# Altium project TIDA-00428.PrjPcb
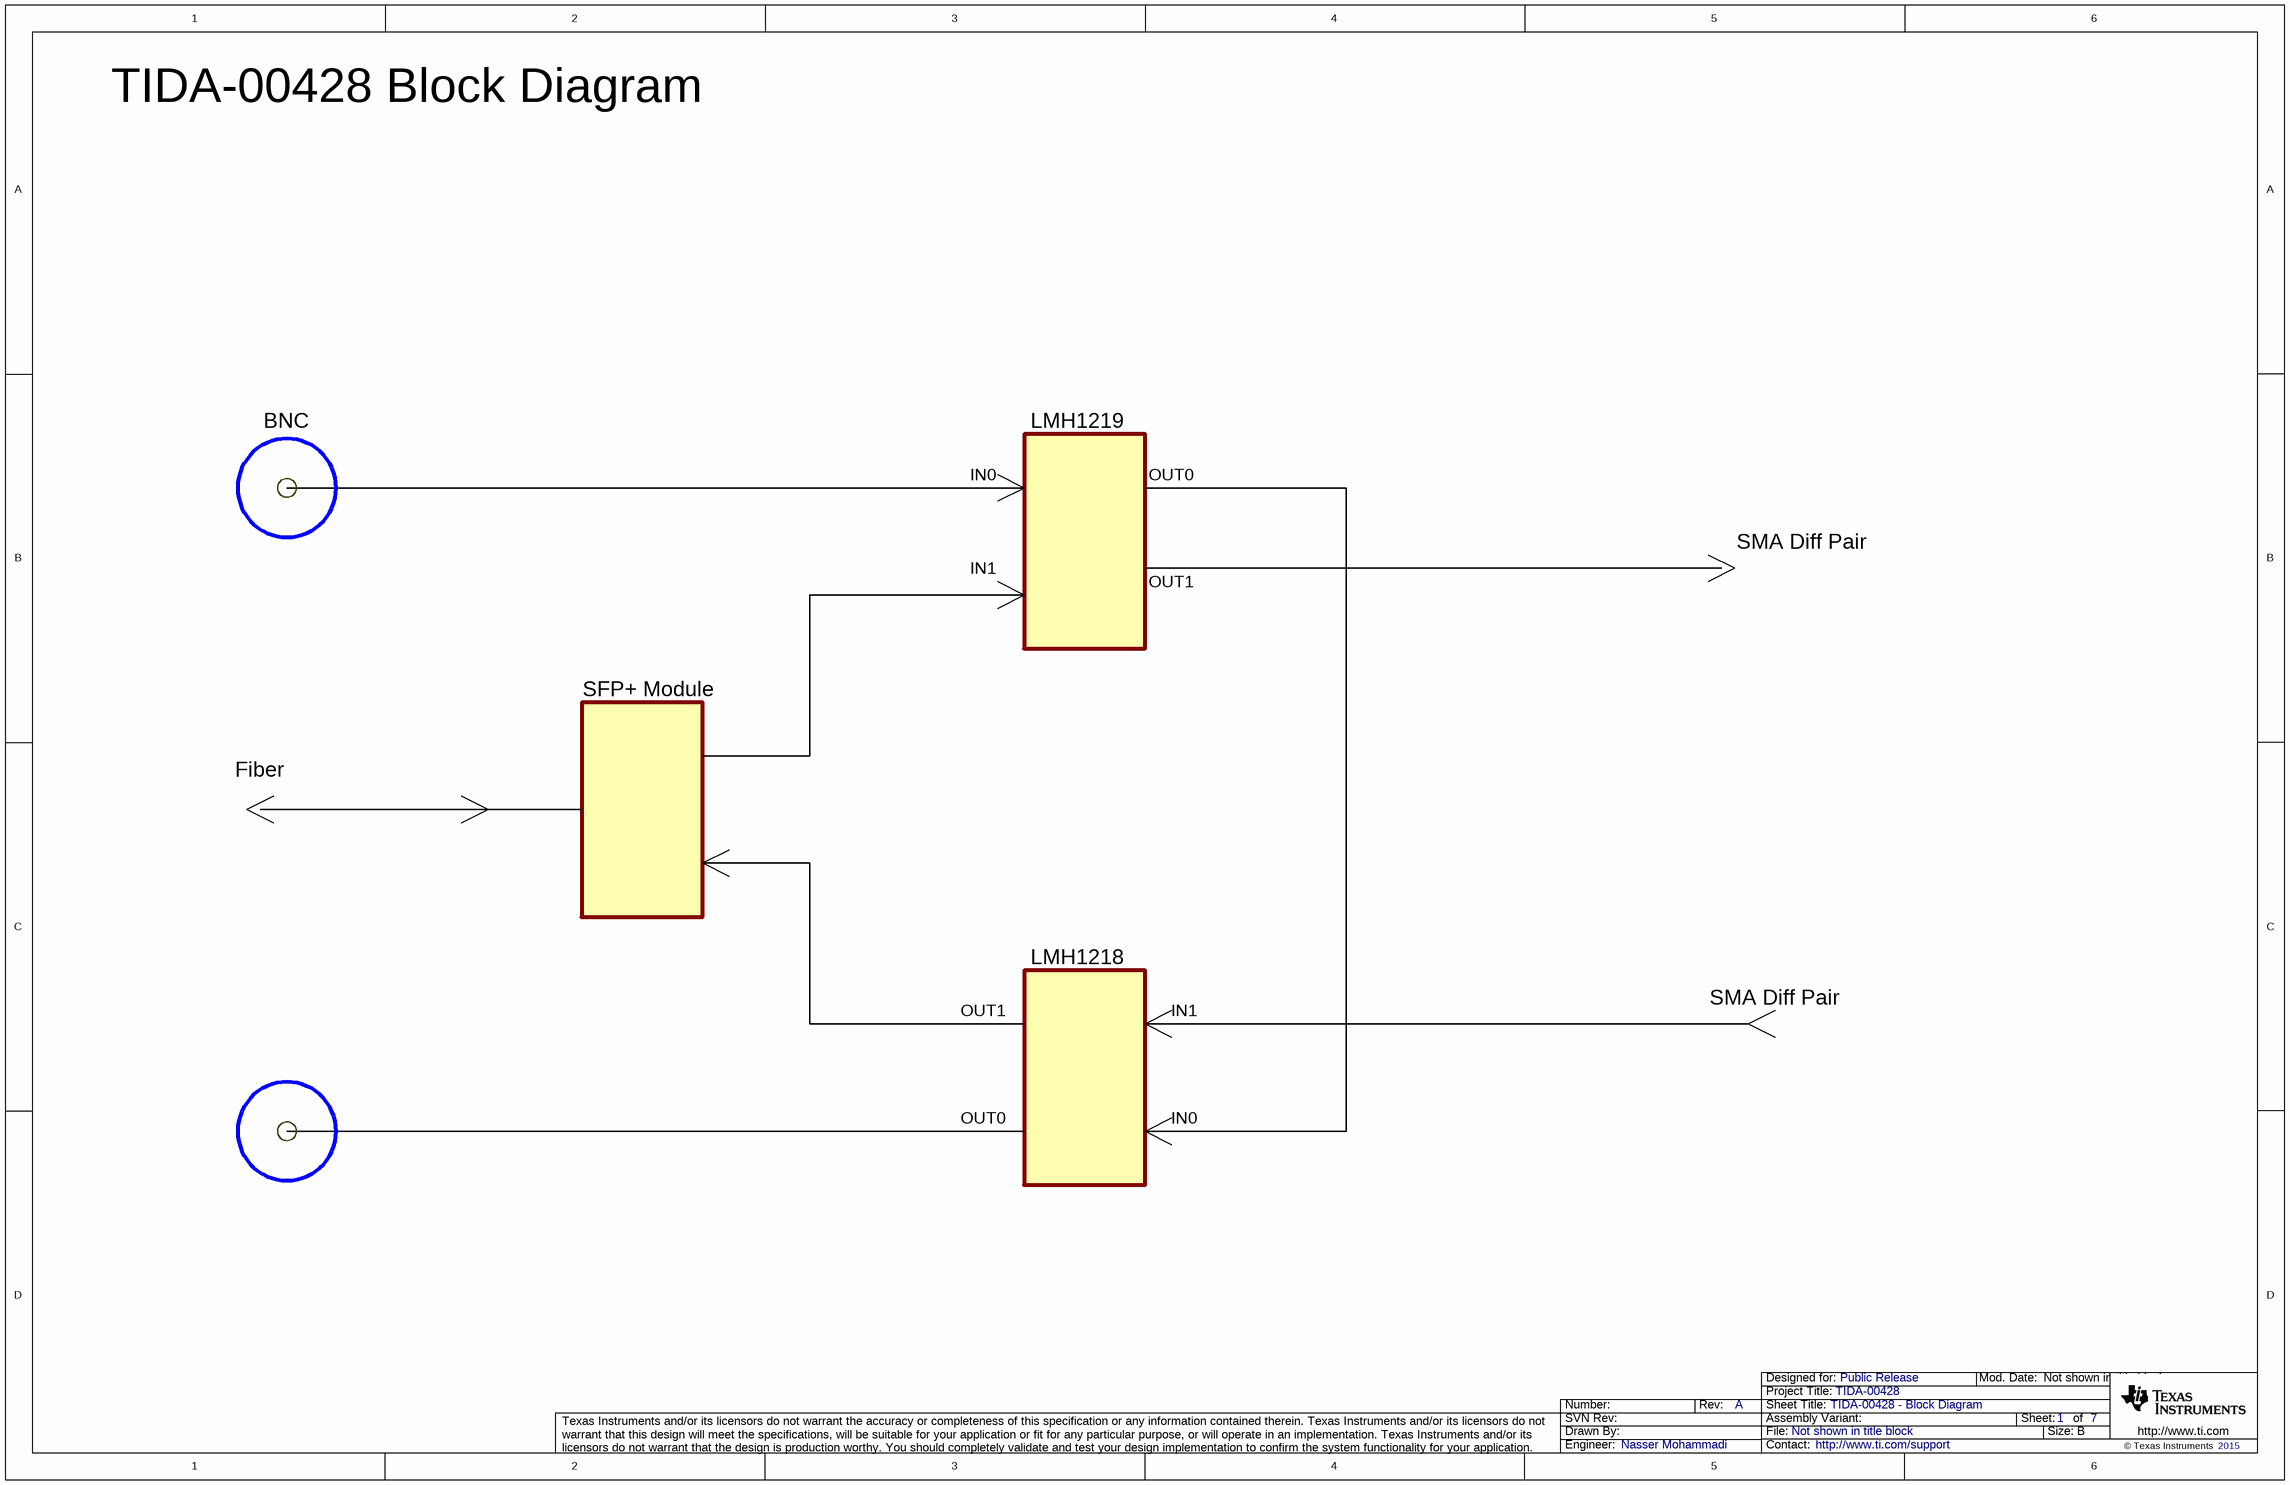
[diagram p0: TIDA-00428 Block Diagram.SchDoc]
CopyrightYear: 2015; PCB_Rev: A; PRJ_Customer: Public Release; PRJ_Engineer: Nasser Mohammadi; PRJ_Title: TIDA-00428; SCH_Rev: A; TechSupport: http://www.ti.com/support
7 sheets, 146 parts. Net scope: global (net labels, ports and power ports of the same name join across sheets).
Sheets:
  TIDA-00428 Block Diagram.SchDoc
  TIDA-00428 LMH1219_Schematic.SchDoc
  TIDA-00428 USB_CNTRL.SchDoc
  TIDA-00428 LMH1218_Schematic.SchDoc
  TIDA-00428 Molex_SFP_Connector.SchDoc
  TIDA-00428 Hardware_ANSI-B.SchDoc
  TIDA-00428 Power.SchDoc

## Sheet TIDA-00428 Block Diagram.SchDoc: TIDA-00428 - Block Diagram
size 431 x 279 mm; Date: Not shown in title block; ApprovedBy: Not shown in title block; CheckedBy: Not shown in title block; Author: Not shown in title block; CompanyName: Not shown in title block; Engineer: Not shown in title block; Organization: Not shown in title block; Address1: Not shown in title block; Address2: Not shown in title block; Address3: Not shown in title block; Address4: Not shown in title block; DocumentNumber: 1; Revision: Use project parameter SCH_Rev; SheetNumber: 1; SheetTotal: 7; PageSetup: Record=PageOptions¦CenterHorizontal=True¦CenterVertical=True¦PrintScale=1.00¦XCorrection=1.00¦YCorrection=1.00¦PrintKind=0¦BorderSize=5000000¦LeftOffset=0¦BottomOffset=0¦Orientation=2¦PaperLength=1000¦PaperWidth=1000¦Scale=100¦PaperSource=15¦PrintQuality=600¦MediaType=1¦DitherType=10¦PaperKind=Letter¦PrintScaleMode=1

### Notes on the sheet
- TIDA-00428 Block Diagram
- BNC
- LMH1219
- IN0
- OUT0
- IN1
- SMA Diff Pair
- OUT1
- SFP+ Module
- Fiber
- LMH1218

## Sheet TIDA-00428 LMH1219_Schematic.SchDoc: TIDA-00428 - LMH1219
size 431 x 279 mm; Date: Not shown in title block; ApprovedBy: Not shown in title block; CheckedBy: Not shown in title block; Author: Not shown in title block; CompanyName: Not shown in title block; Engineer: NasserM; Organization: Not shown in title block; Address1: Not shown in title block; Address2: Not shown in title block; Address3: Not shown in title block; Address4: Not shown in title block; DocumentNumber: 1; Revision: A; SheetNumber: 2; SheetTotal: 7; PageSetup: Record=PageOptions¦CenterHorizontal=True¦CenterVertical=True¦PrintScale=0.59¦XCorrection=1.00¦YCorrection=1.00¦PrintKind=0¦BorderSize=5000000¦LeftOffset=0¦BottomOffset=0¦Orientation=2¦PaperLength=1000¦PaperWidth=1000¦Scale=100¦PaperSource=15¦PrintQuality=600¦MediaType=1¦DitherType=10¦PaperKind=Letter¦PrintScaleMode=1
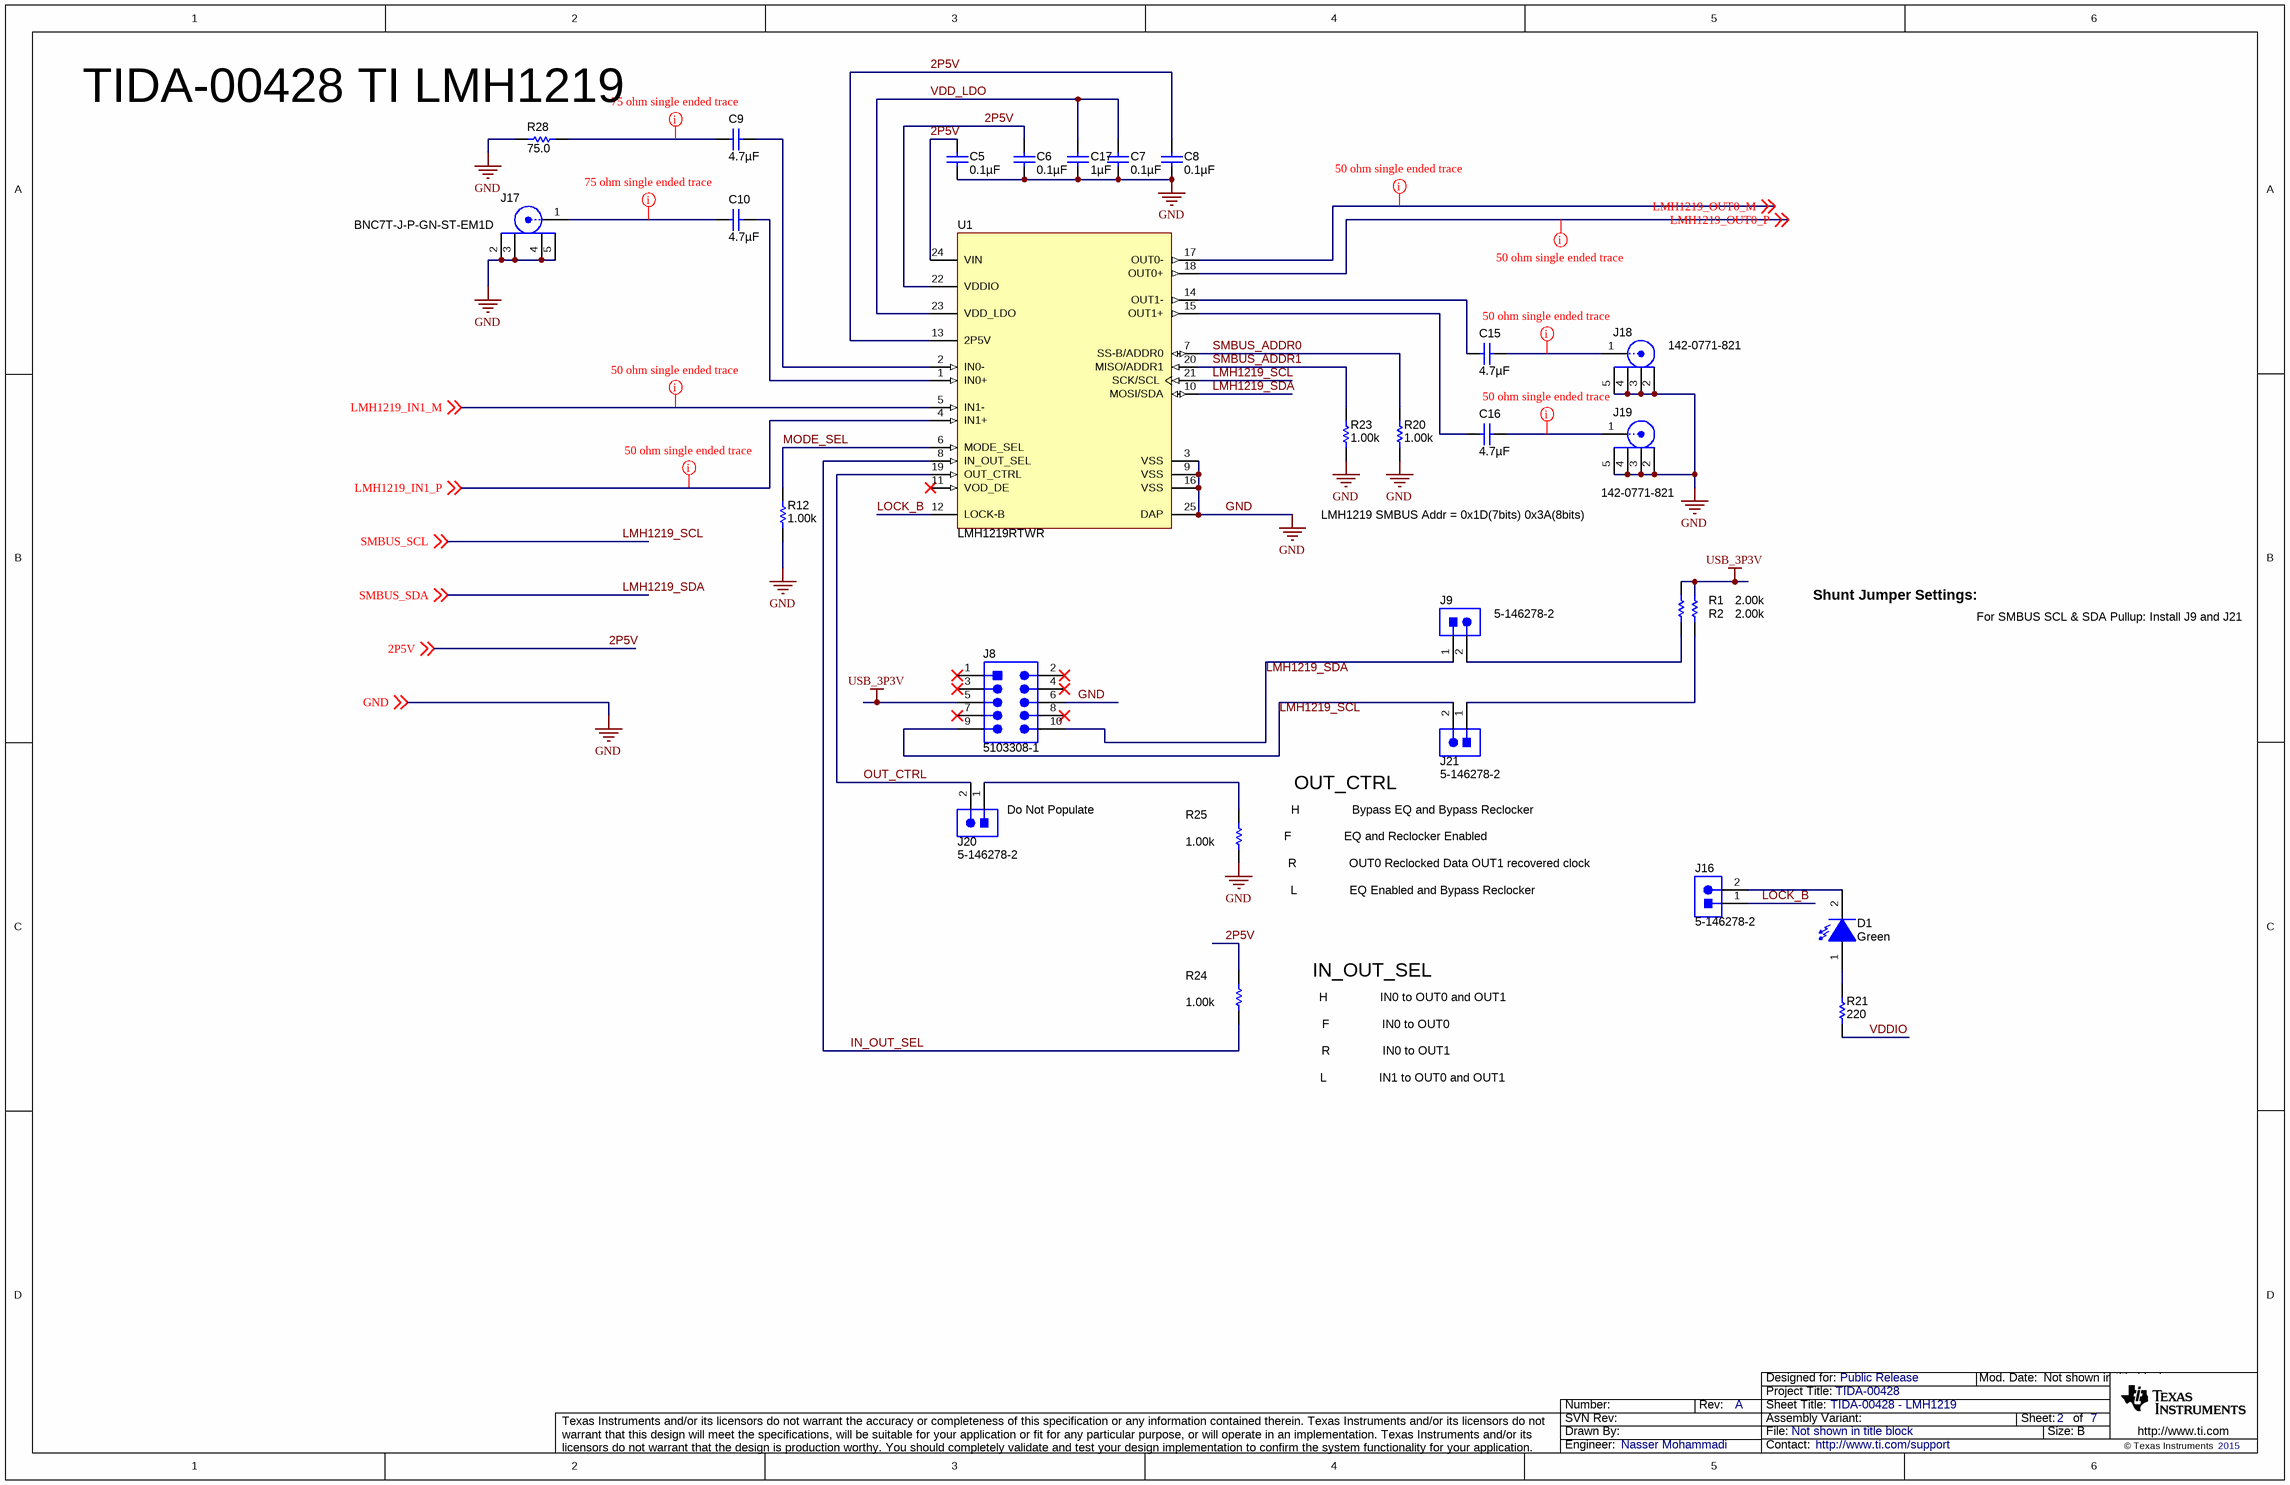
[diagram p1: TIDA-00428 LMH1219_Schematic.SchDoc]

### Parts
C5  ValueDisplayed: 0.1µF  [0402]  (hidden comment: C1005X5R0J104K)
C6  ValueDisplayed: 0.1µF  [0402]  (hidden comment: C1005X5R0J104K)
C7  ValueDisplayed: 0.1µF  [0402]  (hidden comment: C1005X5R0J104K)
C8  ValueDisplayed: 0.1µF  [0402]  (hidden comment: C1005X5R0J104K)
C9  ValueDisplayed: 4.7µF  [0402S]  (hidden comment: C1005X5R1A475K050BC)
C10  ValueDisplayed: 4.7µF  [0402S]  (hidden comment: C1005X5R1A475K050BC)
C15  ValueDisplayed: 4.7µF  [0402S]  (hidden comment: C1005X5R1A475K050BC)
C16  ValueDisplayed: 4.7µF  [0402S]  (hidden comment: C1005X5R1A475K050BC)
C17  ValueDisplayed: 1µF  [0402]  (hidden comment: C1005X5R0J105M)
D1  value Green  [LED_SML-LX0603GW]  (hidden comment: SML-LX0603GW-TR)
J8  5103308-1  [CONN_5103308-1]
J9  5-146278-2  [TE_5-146278-2]
J16  5-146278-2  [TE_5-146278-2]
J17  BNC7T-J-P-GN-ST-EM1D  [SAMTEC_BNC7T-J-P-GN-ST-EM1D]
J18  142-0771-821  [Emerson_142-0771-821]
J19  142-0771-821  [Emerson_142-0771-821]
J20  5-146278-2  [TE_5-146278-2]
J21  5-146278-2  [TE_5-146278-2]
R1  value 2.00k  [0402]  (hidden comment: CRCW04022K00FKED)
R2  value 2.00k  [0402]  (hidden comment: CRCW04022K00FKED)
R12  value 1.00k  [0402]  (hidden comment: CRCW04021K00FKED)
R20  value 1.00k  [0402]  (hidden comment: CRCW04021K00FKED)
R21  value 220  [0402]  (hidden comment: CRCW0402220RJNED)
R23  value 1.00k  [0402]  (hidden comment: CRCW04021K00FKED)
R24  value 1.00k  [0402]  (hidden comment: CRCW04021K00FKED)
R25  value 1.00k  [0402]  (hidden comment: CRCW04021K00FKED)
R28  value 75.0  [0402]  (hidden comment: CRCW040275R0FKED)
U1  LMH1219RTWR  [RTW0024A]

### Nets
2P5V: C5.1 C6.1 C8.1 R24.2 U1.13(2P5V) U1.22(VDDIO) U1.24(VIN) ; off-sheet 2P5V
GND: C5.2 C6.2 C7.2 C8.2 C17.2 J8.6 J17.2 J17.3 J17.4 J17.5 J18.2 J18.3 J18.4 J18.5 J19.2 J19.3 J19.4 J19.5 R12.1 R20.1 R23.1 R25.1 R28.2 U1.3(VSS) U1.9(VSS) U1.16(VSS) U1.25(DAP) ; off-sheet GND
USB_3P3V: J8.5 R1.2 R2.2
IN_OUT_SEL: R24.1 U1.8(IN_OUT_SEL)
LMH1219_IN1_M: U1.5(IN1-) ; off-sheet LMH1219_IN1_M
LMH1219_IN1_P: U1.4(IN1+) ; off-sheet LMH1219_IN1_P
LMH1219_OUT0_M: U1.17(OUT0-) ; off-sheet LMH1219_OUT0_M
LMH1219_OUT0_P: U1.18(OUT0+) ; off-sheet LMH1219_OUT0_P
LMH1219_SCL: J8.9 J21.2 U1.21(SCK/SCL) ; off-sheet SMBUS_SCL  [also labelled SMBUS_SCL]  [project net GPIO1/I2C_SCL]
LMH1219_SDA: J8.10 J9.1 U1.10(MOSI/SDA) ; off-sheet SMBUS_SDA  [also labelled SMBUS_SDA]  [project net GPIO0/I2C_SDA]
LOCK_B: J16.1 U1.12(LOCK-B)
MODE_SEL: R12.2 U1.6(MODE_SEL)
OUT_CTRL: J20.2 U1.19(OUT_CTRL)
SMBUS_ADDR0: R20.2 U1.7(SS-B/ADDR0)
SMBUS_ADDR1: R23.2 U1.20(MISO/ADDR1)
VDD_LDO: C7.1 C17.1 U1.23(VDD_LDO)
VDDIO: R21.1
NetC9_1: C9.1 U1.2(IN0-)
NetC9_2: C9.2 R28.1
NetC10_1: C10.1 U1.1(IN0+)
NetC10_2: C10.2 J17.1
NetC15_1: C15.1 J18.1
NetC15_2: C15.2 U1.14(OUT1-)
NetC16_1: C16.1 J19.1
NetC16_2: C16.2 U1.15(OUT1+)
NetD1_1: D1.1(A) R21.2
NetD1_2: D1.2(K) J16.2
NetJ9_2: J9.2 R1.1
NetJ20_1: J20.1 R25.2
NetJ21_1: J21.1 R2.1

Not connected (* = marked no-connect by the designer): J8 1* 2* 3* 4* 7* 8*; U1 11(VOD_DE)*

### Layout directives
rule Undefined: LMH1219_IN1_M, LMH1219_IN1_P, LMH1219_OUT0_M, LMH1219_OUT0_P, NetC9_2, NetC10_2, NetC15_1, NetC16_1

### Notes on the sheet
- (near R28) TIDA-00428 TI LMH1219
- LMH1219 SMBUS Addr = 0x1D(7bits) 0x3A(8bits)
- Shunt Jumper Settings:
- For SMBUS SCL & SDA Pullup: Install J9 and J21
- (near J20) Do Not Populate
- OUT_CTRL
- (near R25) F               EQ and Reclocker Enabled
- (near R25) H               Bypass EQ and Bypass Reclocker
- (near R25) L               EQ Enabled and Bypass Reclocker
- (near R25) R               OUT0 Reclocked Data OUT1 recovered clock
- IN_OUT_SEL
- F               IN0 to OUT0
- H               IN0 to OUT0 and OUT1
- R               IN0 to OUT1
- L               IN1 to OUT0 and OUT1

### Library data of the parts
C5-C8 = C1005X5R0J104K: CAP, CERM, 0.1uF, 6.3V, +/-10%, X5R, 0402; Manufacturer: TDK; Polarized: N; CompType: Capacitor; U/M: EA; Cap_F: 0.0000001; Tolerance_%: 10; ESR_Ohm: 0.0186; Value1: 0.0186 ohm; VDC_V: 6.3; TaMin_C: -55; TaMax_C: 85
C9 C10 C15 C16 = C1005X5R1A475K050BC: CAP, CERM, 4.7 µF, 10 V, +/- 10%, X5R, 0402; Manufacturer: TDK; Polarized: N; CompType: Capacitor; Value: 4.7uF; U/M: EA; Cap_F: 0.0000047; Tolerance_%: 10; Value1: Unknown; Value2: 10V; TaMin_C: -55; TaMax_C: 85; Cap_Case: 0402
C17 = C1005X5R0J105M: CAP, CERM, 1 µF, 6.3 V, +/- 20%, X5R, 0402; Manufacturer: TDK; Polarized: N; CompType: Capacitor; Value: 1uF; U/M: EA; Cap_F: 0.000001; Tolerance_%: 20; ESR_ohm: 0.0079; Value1: 0.0079 ohm; VDC_V: 6.3; Value2: 6.3V; TaMin_C: -55; TaMax_C: 85
D1 = SML-LX0603GW-TR: LED, Green, SMD; Manufacturer: Lumex; Vf_V: 2.2; Value2: 2.2V; Io_A: 0.02; Tjmax_C: 85; Value1: W; U/M: EA
J8 = 5103308-1: Header (shrouded), 100mil, 5x2, Gold, TH; Manufacturer: TE Connectivity; SymbolCreator: a0412235; U/M: EA
J9 J16 J20 J21 = 5-146278-2: Header, 100mil, 2x1, Tin, TH; Manufacturer: TE Connectivity; SymbolCreator: a0412235; U/M: EA
J17 = BNC7T-J-P-GN-ST-EM1D: Connector, BNC Edge Mount, SMD; Manufacturer: Samtec; SymbolCreator: Altium; U/M: EA
J18 J19 = 142-0771-821: Connector, TH, End launch SMA 50 ohm; Manufacturer: Emerson Network Power; SymbolCreator: X0208326; U/M: EA
R1 R2 = CRCW04022K00FKED: RES, 2.00k ohm, 1%, 0.063W, 0402; Manufacturer: Vishay-Dale; CompType: Resistor; Res_ohm: 2000; Value_Code: 2k00; Tolerance_%: 1; Power_W: 0.063; VDC_V: 50; TempCo: 100 ppm/C; EIA_Code: E96; U/M: EA
R12 R20 R23-R25 = CRCW04021K00FKED: RES, 1.00k ohm, 1%, 0.063W, 0402; Manufacturer: Vishay-Dale; CompType: Resistor; Res_ohm: 1000; Value_Code: 1k00; Tolerance_%: 1; Power_W: 0.063; VDC_V: 50; TempCo: 100 ppm/C; EIA_Code: E96; U/M: EA
R21 = CRCW0402220RJNED: RES, 220 ohm, 5%, 0.063W, 0402; Manufacturer: Vishay-Dale; CompType: Resistor; Value_Code: 220R; Tolerance_%: 5; Power_W: 0.063; VDC_V: 50; TempCo: 200 ppm/C; EIA_Code: E24; U/M: EA
R28 = CRCW040275R0FKED: RES, 75.0 ohm, 1%, 0.063W, 0402; Manufacturer: Vishay-Dale; CompType: Resistor; Res_ohm: 75; Value_Code: 75R0; Tolerance_%: 1; Power_W: 0.063; VDC_V: 50; TempCo: 100 ppm/C; EIA_Code: E96; U/M: EA
U1 = LMH1219RTWR: Low Power 12G UHD Adaptive Cable Equalizer with Integrated Reclocker, RTW0024A; Alternate PartNumber: LMH1219RTWT; Manufacturer: Texas Instruments; SymbolCreator: Altium; CompType: IC; U/M: EA

## Sheet TIDA-00428 USB_CNTRL.SchDoc: TIDA-00428 - USB_CNTRL
size 431 x 279 mm; Date: Not shown in title block; ApprovedBy: Not shown in title block; CheckedBy: Not shown in title block; Author: Not shown in title block; CompanyName: Not shown in title block; DrawnBy: Michael Hinh; Engineer: Not shown in title block; Organization: Not shown in title block; Address1: Not shown in title block; Address2: Not shown in title block; Address3: Not shown in title block; Address4: Not shown in title block; DocumentNumber: 1; Revision: Use project parameter SCH_Rev; SheetNumber: 5; SheetTotal: 7; PageSetup: Record=PageOptions¦CenterHorizontal=True¦CenterVertical=True¦PrintScale=1.00¦XCorrection=1.00¦YCorrection=1.00¦PrintKind=0¦BorderSize=5000000¦LeftOffset=0¦BottomOffset=0¦Orientation=2¦PaperLength=1000¦PaperWidth=1000¦Scale=100¦PaperSource=15¦PrintQuality=600¦MediaType=1¦DitherType=10¦PaperKind=Letter¦PrintScaleMode=1
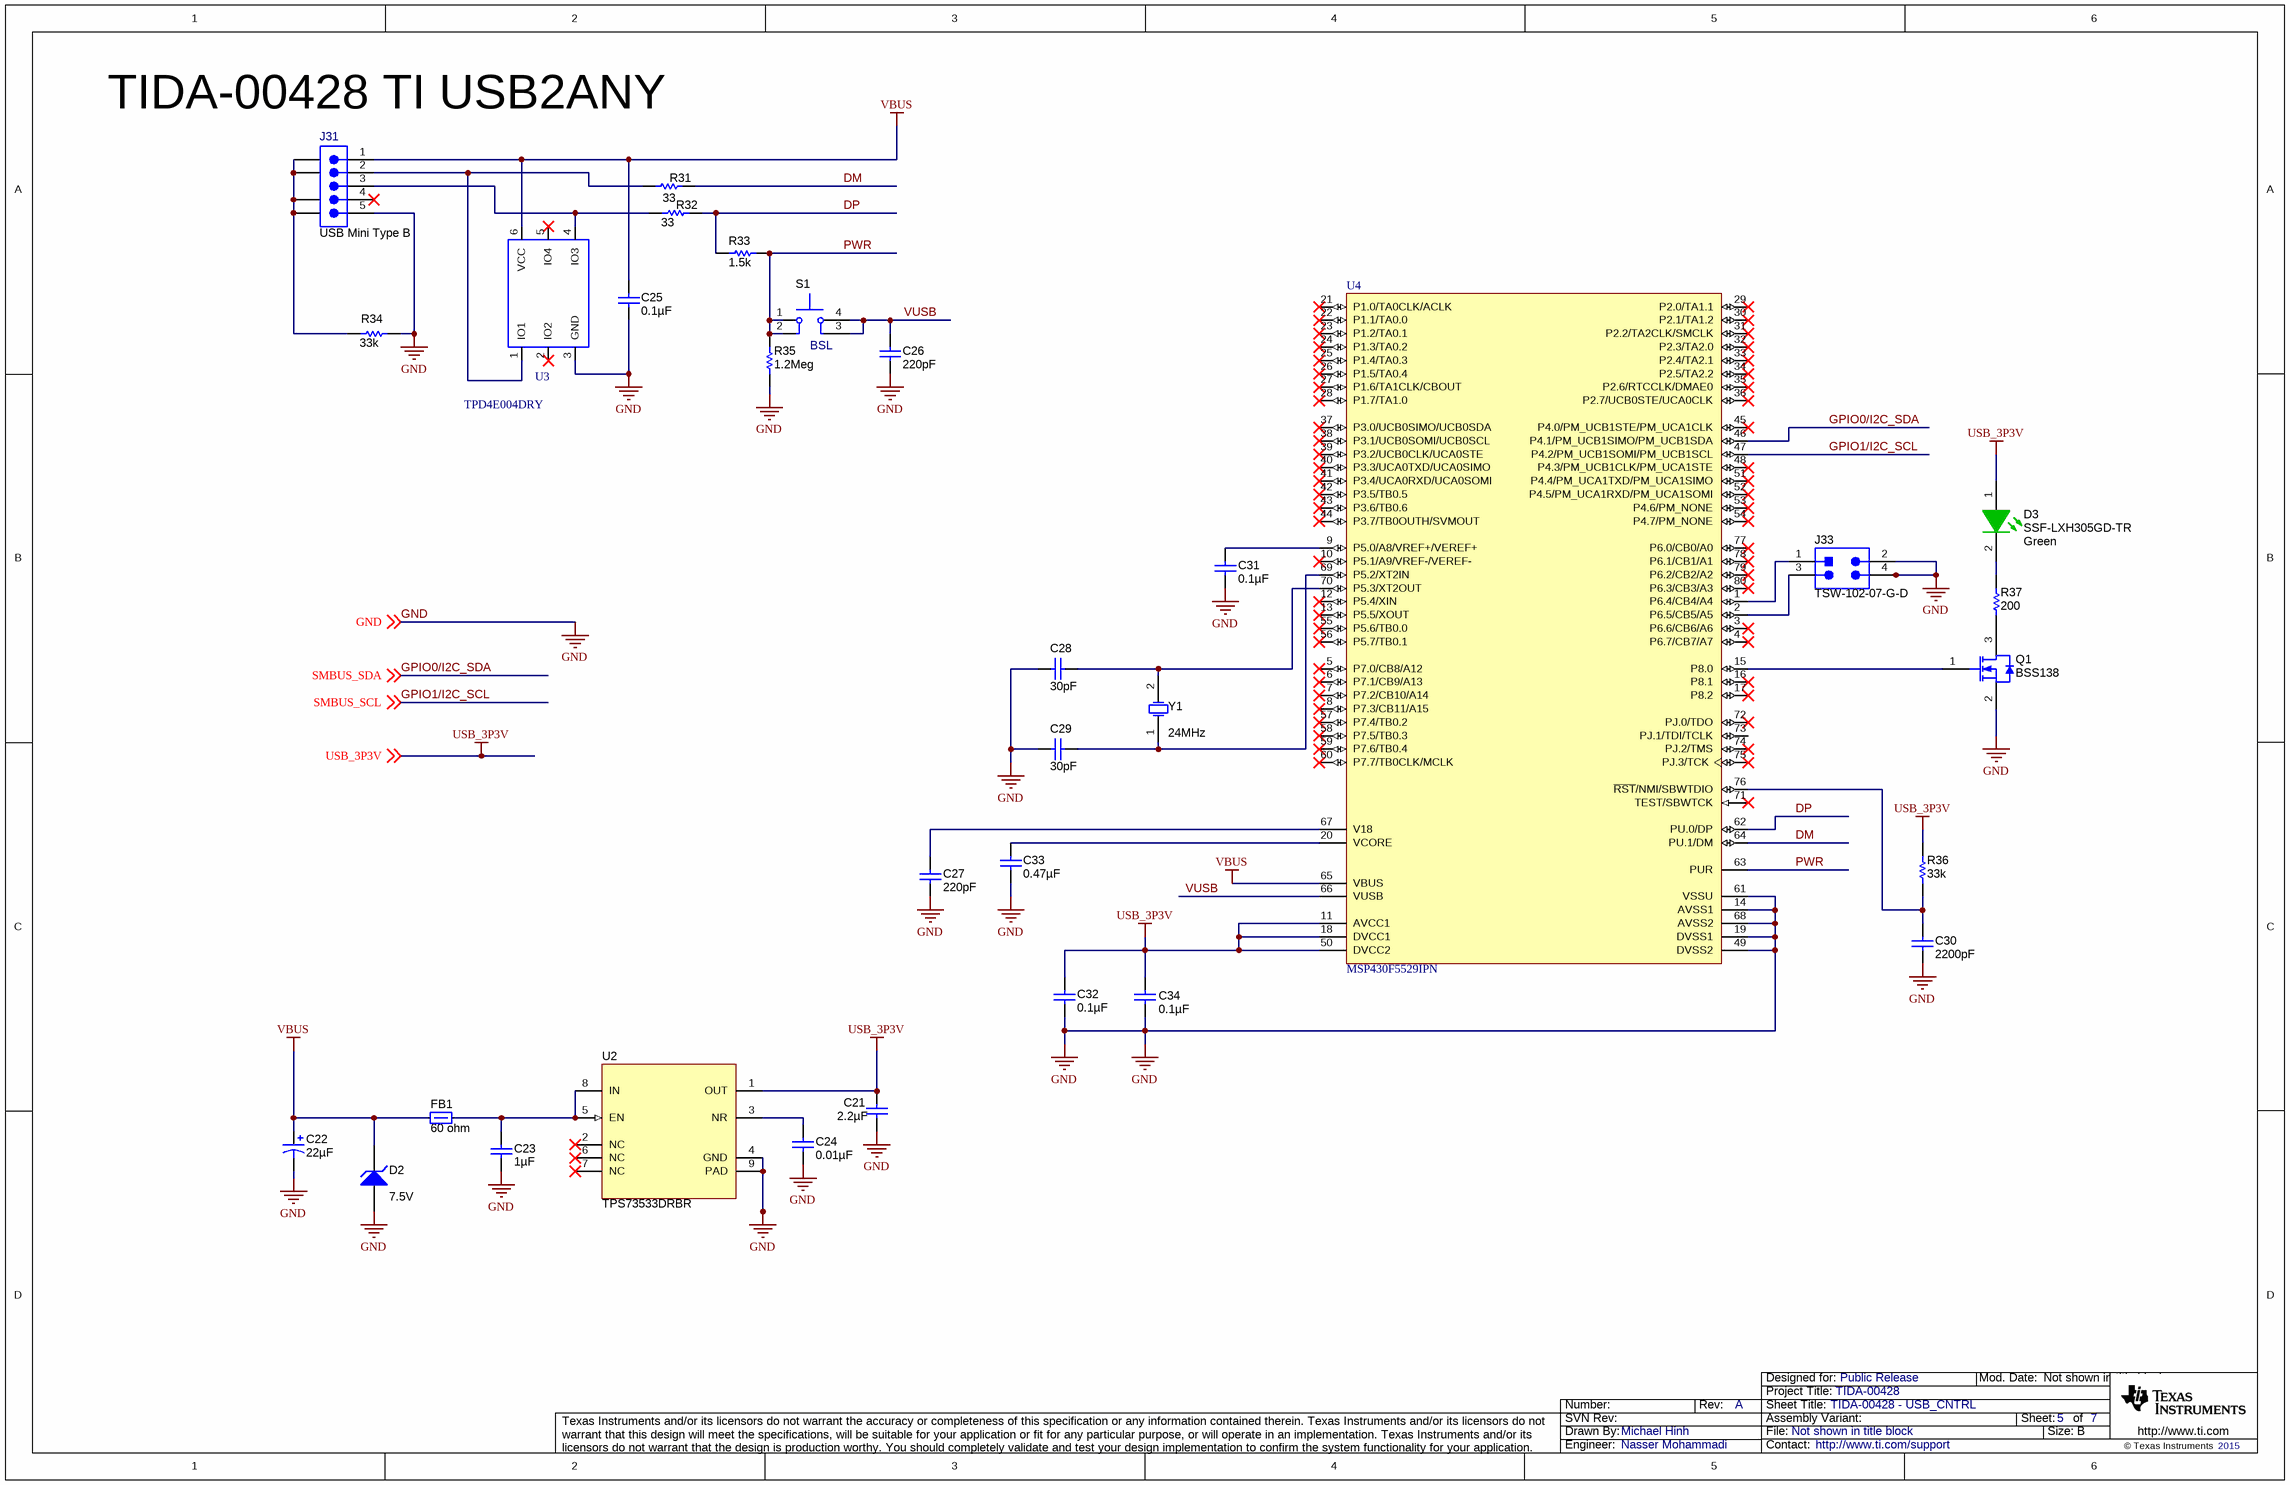
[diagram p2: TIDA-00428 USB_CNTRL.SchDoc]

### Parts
C21  ValueDisplayed: 2.2µF  [C0805]  (hidden comment: 0805YD225KAT2A)
C22  ValueDisplayed: 22µF  [CAPSMT_62_E55]  (hidden comment: EEE-1AA220WR)
C23  ValueDisplayed: 1µF  [C0805]  (hidden comment: C2012X7R1C105K/1.25)
C24  ValueDisplayed: 0.01µF  [C603]  (hidden comment: C1608X7R1H103K)
C25  ValueDisplayed: 0.1µF  [C603]  (hidden comment: 0603YC104JAT2A)
C26  ValueDisplayed: 220pF  [C603]  (hidden comment: 06035A221FAT2A)
C27  ValueDisplayed: 220pF  [C603]  (hidden comment: 06035A221FAT2A)
C28  ValueDisplayed: 30pF  [C603]  (hidden comment: GRM1885C2A300JA01D)
C29  ValueDisplayed: 30pF  [C603]  (hidden comment: GRM1885C2A300JA01D)
C30  ValueDisplayed: 2200pF  [C603]  (hidden comment: C0603X222K5RACTU)
C31  ValueDisplayed: 0.1µF  [C603]  (hidden comment: 0603YC104JAT2A)
C32  ValueDisplayed: 0.1µF  [C603]  (hidden comment: 0603YC104JAT2A)
C33  ValueDisplayed: 0.47µF  [C603]  (hidden comment: GRM188R71A474KA61D)
C34  ValueDisplayed: 0.1µF  [C603]  (hidden comment: 0603YC104JAT2A)
D2  value 7.5V  [SMB]  (hidden comment: 1SMB5922BT3G)
D3  SSF-LXH305GD-TR  value Green  [SSF-LXH305GD_Green]
FB1  value 60 ohm  [0603]  (hidden comment: BK1608HS600-T)
J31  USB Mini Type B  [CONN_USB-Mini-B-1734035-2]
J33  TSW-102-07-G-D  [TSW-102-07-G-D]
Q1  BSS138  [SOT-23]
R31  value 33  [0402]  (hidden comment: CRCW040233R0JNED)
R32  value 33  [0402]  (hidden comment: CRCW040233R0JNED)
R33  value 1.5k  [0402]  (hidden comment: CRCW04021K50JNED)
R34  value 33k  [0402]  (hidden comment: CRCW040233K0JNED)
R35  value 1.2Meg  [R603]  (hidden comment: CRCW06031M20JNEA)
R36  value 33k  [0402]  (hidden comment: CRCW040233K0JNED)
R37  value 200  [R603]  (hidden comment: CRCW0603200RFKEA)
S1  EVQ-PSD02K  [SW_EVQ-PSD02K]  (value not drawn)
U2  TPS73533DRBR  [DRB0008A]
U3  TPD4E004DRY  [DRY]
U4  MSP430F5529IPN  [PN0080A_N]
Y1  Frequency: 24MHz  [XTAL_CSM-7X]  (hidden comment: ECS-240-20-5PX-TR)

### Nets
GND: C21.1 C22.2(-) C23.1 C24.1 C25.1 C26.1 C27.1 C28.2 C29.2 C30.1 C31.1 C32.1 C33.1 C34.1 D2.2(A) J31.5 J33.2 J33.4 Q1.2(S) R34.1 R35.1 U2.4(GND) U2.9(PAD) U3.3(GND) U4.14(AVSS1) U4.19(DVSS1) U4.49(DVSS2) U4.61(VSSU) U4.68(AVSS2) ; off-sheet GND
USB_3P3V: C21.2 C32.2 C34.2 D3.1(A) R36.1 U2.1(OUT) U4.11(AVCC1) U4.18(DVCC1) U4.50(DVCC2) ; off-sheet USB_3P3V
VBUS: C22.1(+) C25.2 D2.1(K) FB1.1 J31.1 U3.6(VCC) U4.65(VBUS)
DM: R31.1 U4.64(PU.1/DM)
DP: R32.1 R33.2 U4.62(PU.0/DP)
GPIO0/I2C_SDA: U4.46(P4.1/PM_UCB1SIMO/PM_UCB1SDA) ; off-sheet SMBUS_SDA  [also labelled SMBUS_SDA]
GPIO1/I2C_SCL: U4.47(P4.2/PM_UCB1SOMI/PM_UCB1SCL) ; off-sheet SMBUS_SCL  [also labelled SMBUS_SCL]
PWR: R33.1 R35.2 S1.1 S1.2 U4.63(PUR)
VUSB: C26.2 S1.3 S1.4 U4.66(VUSB)
NetC23_2: C23.2 FB1.2 U2.5(EN) U2.8(IN)
NetC24_2: C24.2 U2.3(NR)
NetC27_2: C27.2 U4.67(V18)
NetC28_1: C28.1 U4.70(P5.3/XT2OUT) Y1.2(OSC2)
NetC29_1: C29.1 U4.69(P5.2/XT2IN) Y1.1(OSC1)
NetC30_2: C30.2 R36.2 U4.76(~{RST}/NMI/SBWTDIO)
NetC31_2: C31.2 U4.9(P5.0/A8/VREF+/VEREF+)
NetC33_2: C33.2 U4.20(VCORE)
NetD3_2: D3.2(K) R37.2
NetJ31_2: J31.2 R31.2 U3.1(IO1)
NetJ31_3: J31.3 R32.2 U3.4(IO3)
NetJ31_6: J31.6(GND) J31.7(GND) J31.8(GND) J31.9(GND) R34.2
NetJ33_1: J33.1 U4.1(P6.4/CB4/A4)
NetJ33_3: J33.3 U4.2(P6.5/CB5/A5)
NetQ1_1: Q1.1(G) U4.15(P8.0)
NetQ1_3: Q1.3(D) R37.1

Not connected (* = marked no-connect by the designer): J31 4*; U2 2(NC)* 6(NC)* 7(NC)*; U3 2(IO2)* 5(IO4)*; U4 3(P6.6/CB6/A6)* 4(P6.7/CB7/A7)* 5(P7.0/CB8/A12)* 6(P7.1/CB9/A13)* 7(P7.2/CB10/A14)* 8(P7.3/CB11/A15)* 10(P5.1/A9/VREF-/VEREF-)* 12(P5.4/XIN)* 13(P5.5/XOUT)* 16(P8.1)* 17(P8.2)* 21(P1.0/TA0CLK/ACLK)* 22(P1.1/TA0.0)* 23(P1.2/TA0.1)* 24(P1.3/TA0.2)* 25(P1.4/TA0.3)* 26(P1.5/TA0.4)* 27(P1.6/TA1CLK/CBOUT)* 28(P1.7/TA1.0)* 29(P2.0/TA1.1)* 30(P2.1/TA1.2)* 31(P2.2/TA2CLK/SMCLK)* 32(P2.3/TA2.0)* 33(P2.4/TA2.1)* 34(P2.5/TA2.2)* 35(P2.6/RTCCLK/DMAE0)* 36(P2.7/UCB0STE/UCA0CLK)* 37(P3.0/UCB0SIMO/UCB0SDA)* 38(P3.1/UCB0SOMI/UCB0SCL)* 39(P3.2/UCB0CLK/UCA0STE)* 40(P3.3/UCA0TXD/UCA0SIMO)* 41(P3.4/UCA0RXD/UCA0SOMI)* 42(P3.5/TB0.5)* 43(P3.6/TB0.6)* 44(P3.7/TB0OUTH/SVMOUT)* 45(P4.0/PM_UCB1STE/PM_UCA1CLK)* 48(P4.3/PM_UCB1CLK/PM_UCA1STE)* 51(P4.4/PM_UCA1TXD/PM_UCA1SIMO)* 52(P4.5/PM_UCA1RXD/PM_UCA1SOMI)* 53(P4.6/PM_NONE)* 54(P4.7/PM_NONE)* 55(P5.6/TB0.0)* 56(P5.7/TB0.1)* 57(P7.4/TB0.2)* 58(P7.5/TB0.3)* 59(P7.6/TB0.4)* 60(P7.7/TB0CLK/MCLK)* 71(TEST/SBWTCK)* 72(PJ.0/TDO)* 73(PJ.1/TDI/TCLK) 74(PJ.2/TMS)* 75(PJ.3/TCK)* 77(P6.0/CB0/A0)* 78(P6.1/CB1/A1)* 79(P6.2/CB2/A2)* 80(P6.3/CB3/A3)*

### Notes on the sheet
- (near J31) TIDA-00428 TI USB2ANY
- (near S1) BSL

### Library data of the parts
C21 = 0805YD225KAT2A: CAP, CERM, 2.2uF, 16V, +/-10%, X5R, 0805; Manufacturer: AVX; Polarized: N; CompType: Capacitor; U/M: EA; Cap_F: 0.0000022; Tolerance_%: 10; ESR_Ohm: 0.009; Value1: 0.009 ohm; VDC_V: 16; TaMin_C: -55; TaMax_C: 85; Cap_Case: 0805
C22 = EMVE100ADA220ME55G: CAP ALUM 22UF 10V 20% SMD; Manufacturer: Panasonic - ECG; Polarized: Y; CompType: Capacitor; U/M: EA; Cap_F: 0.000022; Tolerance_%: 20; VDC_V: 10; IRMS_A: 0.03; TaMin_C: -40; TaMax_C: 105; Cap_Case: E55
C23 = C2012Y5V1C105Z/0.85: CAP CER 1UF 16V 10% X7R 0805; Manufacturer: TDK; Polarized: N; CompType: Capacitor; U/M: EA; Cap_F: 0.000001; Tolerance_%: 80; ESR_Ohm: 0.009; Value1: 0.009 ohm; VDC_V: 16; TaMin_C: -30; TaMax_C: 85; Cap_Case: 0805
C24 = C1608X7R1H103K: CAP, CERM, 0.01uF, 50V, +/-10%, X7R, 0603; Manufacturer: TDK; Polarized: N; CompType: Capacitor; U/M: EA; Cap_F: 0.00000001; Tolerance_%: 10; ESR_Ohm: 0.0539; Value1: 0.0539 ohm; VDC_V: 50; TaMin_C: -55; TaMax_C: 125; Cap_Case: 0603
C25 C31 C32 C34 = 0603YC104JAT2A: CAP, CERM, 0.1uF, 16V, +/-5%, X7R, 0603; Manufacturer: AVX; Polarized: N; CompType: Capacitor; U/M: EA; Cap_F: 0.0000001; Tolerance_%: 5; ESR_Ohm: 0.039; Value1: 0.039 ohm; VDC_V: 16; TaMin_C: -55; TaMax_C: 125; Cap_Case: 0603
C26 C27 = 06035A221FAT2A: CAP, CERM, 220pF, 50V, +/-1%, C0G/NP0, 0603; Manufacturer: AVX; Polarized: N; CompType: Capacitor; U/M: EA; Cap_F: 0.00000000022; Tolerance_%: 1; ESR_Ohm: 0.083; Value1: 0.083 ohm; VDC_V: 50; TaMin_C: -55; TaMax_C: 125; Cap_Case: 0603
C28 C29 = GRM1885C2A300JA01D: CAP, CERM, 30pF, 100V, +/-5%, C0G/NP0, 0603; Manufacturer: MuRata; Polarized: N; CompType: Capacitor; U/M: EA; Cap_F: 0.00000000003; Tolerance_%: 5; VDC_V: 100; TaMin_C: -55; TaMax_C: 125; Cap_Case: 0603
C30 = C0603X222K5RACTU: CAP, CERM, 2200pF, 50V, +/-10%, X7R, 0603; Manufacturer: Kemet; Polarized: N; CompType: Capacitor; U/M: EA; Cap_F: 0.0000000022; Tolerance_%: 10; VDC_V: 50; TaMin_C: -55; TaMax_C: 125; Cap_Case: 0603
C33 = GRM188R71A474KA61D: CAP, CERM, 0.47uF, 10V, +/-10%, X7R, 0603; Manufacturer: MuRata; Polarized: N; CompType: Capacitor; U/M: EA; Cap_F: 0.00000047; Tolerance_%: 10; TaMin_C: -55; TaMax_C: 125; Cap_Case: 0603
D2 = 1SMB5922BT3G: Diode, Zener, 7.5 V, 550 mW, SMB; Manufacturer: ON Semiconductor; SymbolCreator: a0412235; U/M: EA; Power_W: 0.55; Vz_V: 7.5; Value1: 0.55W; RJA_CperW: 226
D3 = SSF-LXH305GD-TR: LED, Green, SMD; Manufacturer: Lumex; SymbolCreator: Altium; Vf_V: 2.2; Value2: 2.2V; Io_A: 0.02; Vr_V: 5; Ir_A: 0.0001; Tjmax_C: 85; Value1: W; Angle: 60; U/M: EA
FB1 = BK1608HS600-T: Ferrite Bead, 60 ohm @ 100 MHz, 0.8 A, 0603; Manufacturer: Taiyo Yuden; Imax_A: 0.8; DCR_ohm: 0.1; Value1: 0.1 ohm; Value2: 0.8A; ZTyp@100MHz_Ohm: 60
J31 = 1734035-2: Connector, Receptacle, Mini-USB Type B, R/A, Top Mount SMT; Manufacturer: TE Connectivity; SymbolCreator: A0412235; U/M: EA
J33 = TSW-102-07-G-D: Header, 100mil, 2x2, Gold, TH; Manufacturer: Samtec; SymbolCreator: a0412235; U/M: EA
Q1 = BSS138: MOSFET, N-CH, 50 V, 0.22 A, SOT-23; Manufacturer: Fairchild Semiconductor; Alternate Manufacturer: None; U/M: EA; ChType: N; Value: 50V; VdsMax_V: 50; Value1: 6 ohm; Rdson45_ohm: 6; Value2: 1.7 nC; QgTyp_nC: 1.7; Vgs_V: 20; IdsMax_A: 0.22
R31 R32 = CRCW040233R0JNED: RES, 33 ohm, 5%, 0.063W, 0402; Manufacturer: Vishay-Dale; CompType: Resistor; Value_Code: 33R0; Tolerance_%: 5; Power_W: 0.063; VDC_V: 50; TempCo: 200 ppm/C; EIA_Code: E24; U/M: EA
R33 = CRCW04021K50JNED: RES, 1.5k ohm, 5%, 0.063W, 0402; Manufacturer: Vishay-Dale; CompType: Resistor; Res_ohm: 1500; Value_Code: 1k50; Tolerance_%: 5; Power_W: 0.063; VDC_V: 50; TempCo: 200 ppm/C; EIA_Code: E24; U/M: EA
R34 R36 = CRCW040233K0JNED: RES, 33k ohm, 5%, 0.063W, 0402; Manufacturer: Vishay-Dale; CompType: Resistor; Res_ohm: 33000; Value_Code: 33k0; Tolerance_%: 5; Power_W: 0.063; VDC_V: 50; TempCo: 200 ppm/C; EIA_Code: E24; U/M: EA
R35 = CRCW06031M20JNEA: RES, 1.2Meg ohm, 5%, 0.1W, 0603; Manufacturer: Vishay-Dale; CompType: Resistor; Res_ohm: 1200000; Value_Code: 1M20; Tolerance_%: 5; Power_W: 0.1; VDC_V: 75; TempCo: 200 ppm/C; EIA_Code: E24; U/M: EA
R37 = CRCW0603200RFKEA: RES, 200 ohm, 1%, 0.1W, 0603; Manufacturer: Vishay-Dale; CompType: Resistor; Value_Code: 200R; Tolerance_%: 1; Power_W: 0.1; VDC_V: 75; TempCo: 100 ppm/C; EIA_Code: E96; U/M: EA
S1 = EVQ-PSD02K: Switch, Tactile, SPST-NO, SMT; Manufacturer: Panasonic; SymbolCreator: a0799628; VDC_V: 12; SwitchFunction: Off-Mom; PositionCount: 1; CurrentRating_mA: 50
U2 = TPS73533DRBR: 500mA, Low Quiescent Current, Ultra-Low Noise, High PSRR Low-Dropout Linear Regulator, DRB0008A; Manufacturer: Texas Instruments; Alternate PartNumber: TPS73533DRBT; SymbolCreator: Altium; CompType: IC; U/M: EA
U3 = TPD4E004DRY: IC, 4-Chan ESD-Protection Array; Manufacturer: Texas Instruments; Second Source: C:\program files\p-cad 2004\pcad_pdf's\tpd4e004.pdf; Reference: \\vette02\pmp_pcb\pcad_pdf's\tpd4e004.pdf; Area: 3.883 mm
U4 = MSP430F5529IPN: 25 MHz Mixed Signal Microcontroller with 128 KB Flash, 8192 B SRAM and 63 GPIOs, -40 to 85 degC, 80-pin QFP (PN), Green (RoHS & no Sb/Br); Manufacturer: Texas Instruments; Alternate PartNumber: Equivalent; ADC: 12-bit SAR; ADC Channels: 16; Brown Out Reset: Yes; DMA: 3; Flash(KB): 128; Frequency(MHz): 25; GPIO: 63; Multiplier: 32x32; Pin/Package: 0DIESALE, 80LQFP; SRAM(B): 8192; SubFamily: 5 Series; Timers - 16-bit: 4; USB: 1; USCI_A (UART/LIN/IrDA/SPI): 2
Y1 = ECS-240-20-5PX-TR: Crystal, 24.000MHz, 20pF, SMD; Manufacturer: ECS Inc.; SymbolCreator: a0412235; U/M: EA; TaMin_C: -10; TaMax_C: 70; Frequency Stability: ±50ppm

## Sheet TIDA-00428 LMH1218_Schematic.SchDoc: TIDA-00428 - LMH1218
size 431 x 279 mm; Date: Not shown in title block; ApprovedBy: Not shown in title block; CheckedBy: Not shown in title block; Author: Not shown in title block; CompanyName: Not shown in title block; Engineer: Nasser; Organization: Not shown in title block; Address1: Not shown in title block; Address2: Not shown in title block; Address3: Not shown in title block; Address4: Not shown in title block; DocumentNumber: 1; Revision: Use project parameter SCH_Rev; SheetNumber: 3; SheetTotal: 7; PageSetup: Record=PageOptions¦CenterHorizontal=True¦CenterVertical=True¦PrintScale=1.00¦XCorrection=1.00¦YCorrection=1.00¦PrintKind=0¦BorderSize=5000000¦LeftOffset=0¦BottomOffset=0¦Orientation=2¦PaperLength=1000¦PaperWidth=1000¦Scale=100¦PaperSource=15¦PrintQuality=600¦MediaType=1¦DitherType=10¦PaperKind=Letter¦PrintScaleMode=1
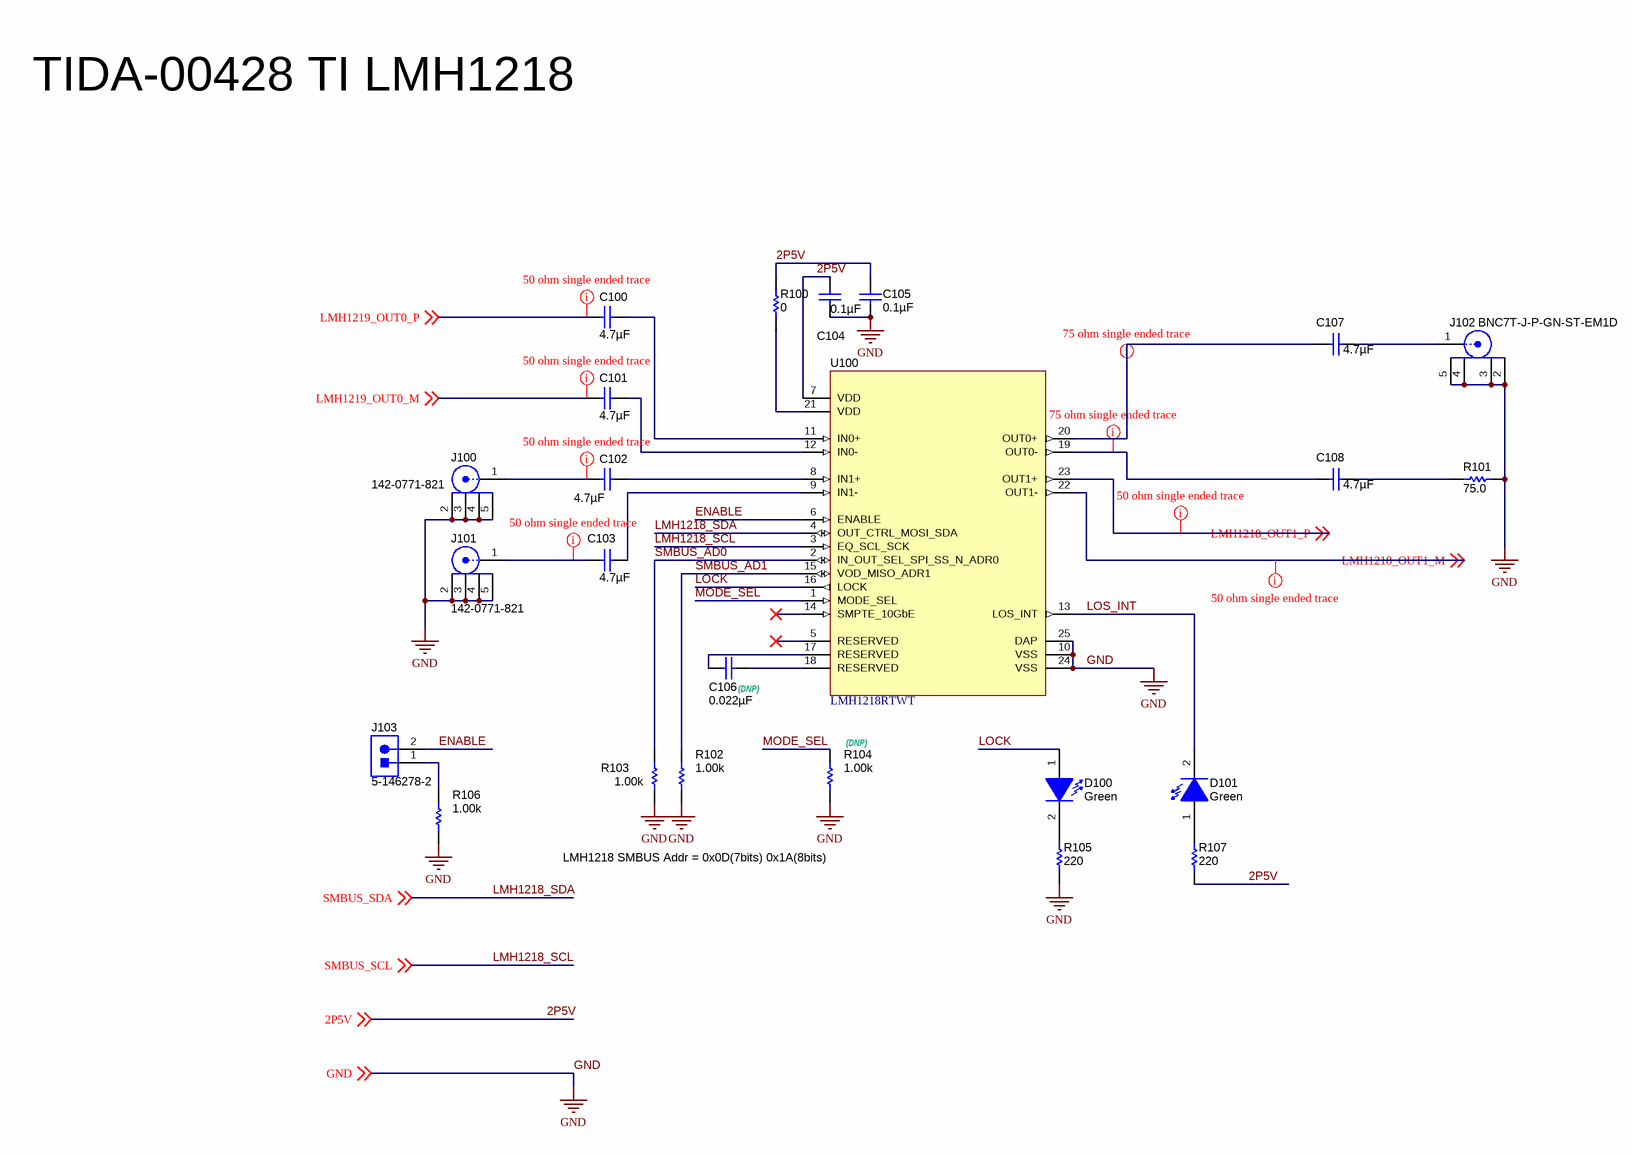
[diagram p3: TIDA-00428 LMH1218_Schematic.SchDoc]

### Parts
C100  ValueDisplayed: 4.7µF  [0402]  (hidden comment: C1005X5R0J475M050BC)
C101  ValueDisplayed: 4.7µF  [0402]  (hidden comment: C1005X5R0J475M050BC)
C102  ValueDisplayed: 4.7µF  [0402]  (hidden comment: C1005X5R0J475M050BC)
C103  ValueDisplayed: 4.7µF  [0402]  (hidden comment: C1005X5R0J475M050BC)
C104  ValueDisplayed: 0.1µF  [0402]  (hidden comment: C1005X5R0J104K)
C105  ValueDisplayed: 0.1µF  [0402]  (hidden comment: C1005X5R0J104K)
C106  ValueDisplayed: 0.022µF  [0402]  (hidden comment: GRM155R61C223KA01D)
C107  ValueDisplayed: 4.7µF  [0402]  (hidden comment: C1005X5R0J475M050BC)
C108  ValueDisplayed: 4.7µF  [0402]  (hidden comment: C1005X5R0J475M050BC)
D100  value Green  [LED_SML-LX0603GW]  (hidden comment: SML-LX0603GW-TR)
D101  value Green  [LED_SML-LX0603GW]  (hidden comment: SML-LX0603GW-TR)
J100  142-0771-821  [Emerson_142-0771-821]
J101  142-0771-821  [Emerson_142-0771-821]
J102  BNC7T-J-P-GN-ST-EM1D  [SAMTEC_BNC7T-J-P-GN-ST-EM1D]
J103  5-146278-2  [TE_5-146278-2]
R100  ValueDisplayed: 0  [0603]  (hidden comment: CRCW06030000Z0EA)
R101  value 75.0  [0402]  (hidden comment: CRCW040275R0FKED)
R102  value 1.00k  [0402]  (hidden comment: CRCW04021K00FKED)
R103  value 1.00k  [0402]  (hidden comment: CRCW04021K00FKED)
R104  value 1.00k  [0402]  (hidden comment: CRCW04021K00FKED)
R105  value 220  [0402]  (hidden comment: CRCW0402220RJNED)
R106  value 1.00k  [0402]  (hidden comment: CRCW04021K00FKED)
R107  value 220  [0402]  (hidden comment: CRCW0402220RJNED)
U100  LMH1218RTWT  [RTW0024A]

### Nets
2P5V: C104.1 C105.1 R100.2 R107.1 U100.7(VDD) ; off-sheet 2P5V
GND: C104.2 C105.2 J100.2 J100.3 J100.4 J100.5 J101.2 J101.3 J101.4 J101.5 J102.2 J102.3 J102.4 J102.5 R101.1 R102.1 R103.1 R104.1 R105.1 R106.1 U100.10(VSS) U100.24(VSS) U100.25(DAP) ; off-sheet GND
ENABLE: J103.2 U100.6(ENABLE)
LMH1218_OUT1_M: U100.22(OUT1-) ; off-sheet LMH1218_OUT1_M
LMH1218_OUT1_P: U100.23(OUT1+) ; off-sheet LMH1218_OUT1_P
LMH1218_SCL: U100.3(EQ_SCL_SCK) ; off-sheet SMBUS_SCL  [also labelled SMBUS_SCL]  [project net GPIO1/I2C_SCL]
LMH1218_SDA: U100.4(OUT_CTRL_MOSI_SDA) ; off-sheet SMBUS_SDA  [also labelled SMBUS_SDA]  [project net GPIO0/I2C_SDA]
LMH1219_OUT0_M: C101.2 ; off-sheet LMH1219_OUT0_M
LMH1219_OUT0_P: C100.2 ; off-sheet LMH1219_OUT0_P
LOCK: D100.1(A) U100.16(LOCK)
LOS_INT: D101.2(K) U100.13(LOS_INT)
MODE_SEL: R104.2 U100.1(MODE_SEL)
SMBUS_AD0: R103.2 U100.2(IN_OUT_SEL_SPI_SS_N_ADR0)
SMBUS_AD1: R102.2 U100.15(VOD_MISO_ADR1)
NetC100_1: C100.1 U100.11(IN0+)
NetC101_1: C101.1 U100.12(IN0-)
NetC102_1: C102.1 U100.8(IN1+)
NetC102_2: C102.2 J100.1
NetC103_1: C103.1 U100.9(IN1-)
NetC103_2: C103.2 J101.1
NetC106_1: C106.1 U100.18(RESERVED)
NetC106_2: C106.2 U100.17(RESERVED)
NetC107_1: C107.1 J102.1
NetC107_2: C107.2 U100.20(OUT0+)
NetC108_1: C108.1 R101.2
NetC108_2: C108.2 U100.19(OUT0-)
NetD100_2: D100.2(K) R105.2
NetD101_1: D101.1(A) R107.2
NetJ103_1: J103.1 R106.2
NetR100_1: R100.1 U100.21(VDD)

Not connected (* = marked no-connect by the designer): U100 5(RESERVED)* 14(SMPTE_10GbE)*

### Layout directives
rule Undefined: LMH1218_OUT1_M, LMH1218_OUT1_P, LMH1219_OUT0_M, LMH1219_OUT0_P, NetC102_2, NetC103_2, NetC107_2, NetC108_2

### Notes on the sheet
- TIDA-00428 TI LMH1218
- (near C106) (DNP)
- (near R104) (DNP)
- LMH1218 SMBUS Addr = 0x0D(7bits) 0x1A(8bits)

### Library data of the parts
C100-C103 C107 C108 = C1005X5R0J475M050BC: CAP, CERM, 4.7uF, 6.3V, +/-20%, X5R, 0402; Manufacturer: TDK; Polarized: N; CompType: Capacitor; U/M: EA; Cap_F: 0.0000047; Tolerance_%: 20; Value1: Unknown; VDC_V: 6.3; TaMin_C: -55; TaMax_C: 85
C104 C105 = C1005X5R0J104K: as C5 on sheet TIDA-00428 LMH1219_Schematic
C106 = GRM155R61C223KA01D: CAP, CERM, 0.022uF, 16V, +/-10%, X5R, 0402; Manufacturer: MuRata; Polarized: N; CompType: Capacitor; U/M: EA; Cap_F: 0.000000022; Tolerance_%: 10; Value1: Unknown; VDC_V: 16; TaMin_C: -55; TaMax_C: 85
D100 D101 = SML-LX0603GW-TR: as D1 on sheet TIDA-00428 LMH1219_Schematic
J100 J101 = 142-0771-821: as J18 on sheet TIDA-00428 LMH1219_Schematic
J102 = BNC7T-J-P-GN-ST-EM1D: as J17 on sheet TIDA-00428 LMH1219_Schematic
J103 = 5-146278-2: as J9 on sheet TIDA-00428 LMH1219_Schematic
R100 = CRCW06030000Z0EA: RES, 0, 5%, 0.1 W, 0603; Manufacturer: Vishay-Dale; CompType: Resistor; Value: 0; Value_Code: 0000; Tolerance_%: 5; Power_W: 0.1; Value2: 0.1W; VDC_V: 75; TempCo: 200 ppm/C; EIA_Code: E24; U/M: EA
R101 = CRCW040275R0FKED: as R28 on sheet TIDA-00428 LMH1219_Schematic
R102-R104 R106 = CRCW04021K00FKED: as R12 on sheet TIDA-00428 LMH1219_Schematic
R105 R107 = CRCW0402220RJNED: as R21 on sheet TIDA-00428 LMH1219_Schematic
U100 = LMH1218SQA: Ultra HD Low-Power SDI Reclocker and Cable Driver, RTW0024A; Alternate Manufacturer: None; Manufacturer: Texas Instruments; SymbolCreator: Altium; CompType: IC; U/M: EA

## Sheet TIDA-00428 Molex_SFP_Connector.SchDoc: TIDA-00428 - SFP
size 431 x 279 mm; Date: Not shown in title block; ApprovedBy: Not shown in title block; CheckedBy: Not shown in title block; Author: Not shown in title block; CompanyName: Not shown in title block; Engineer: Not shown in title block; Organization: Not shown in title block; Address1: Not shown in title block; Address2: Not shown in title block; Address3: Not shown in title block; Address4: Not shown in title block; DocumentNumber: 1; Revision: Use project parameter SCH_Rev; SheetNumber: 4; SheetTotal: 7; PageSetup: Record=PageOptions¦CenterHorizontal=True¦CenterVertical=True¦PrintScale=1.00¦XCorrection=1.00¦YCorrection=1.00¦PrintKind=0¦BorderSize=5000000¦LeftOffset=0¦BottomOffset=0¦Orientation=2¦PaperLength=1000¦PaperWidth=1000¦Scale=100¦PaperSource=15¦PrintQuality=600¦MediaType=1¦DitherType=10¦PaperKind=Letter¦PrintScaleMode=1
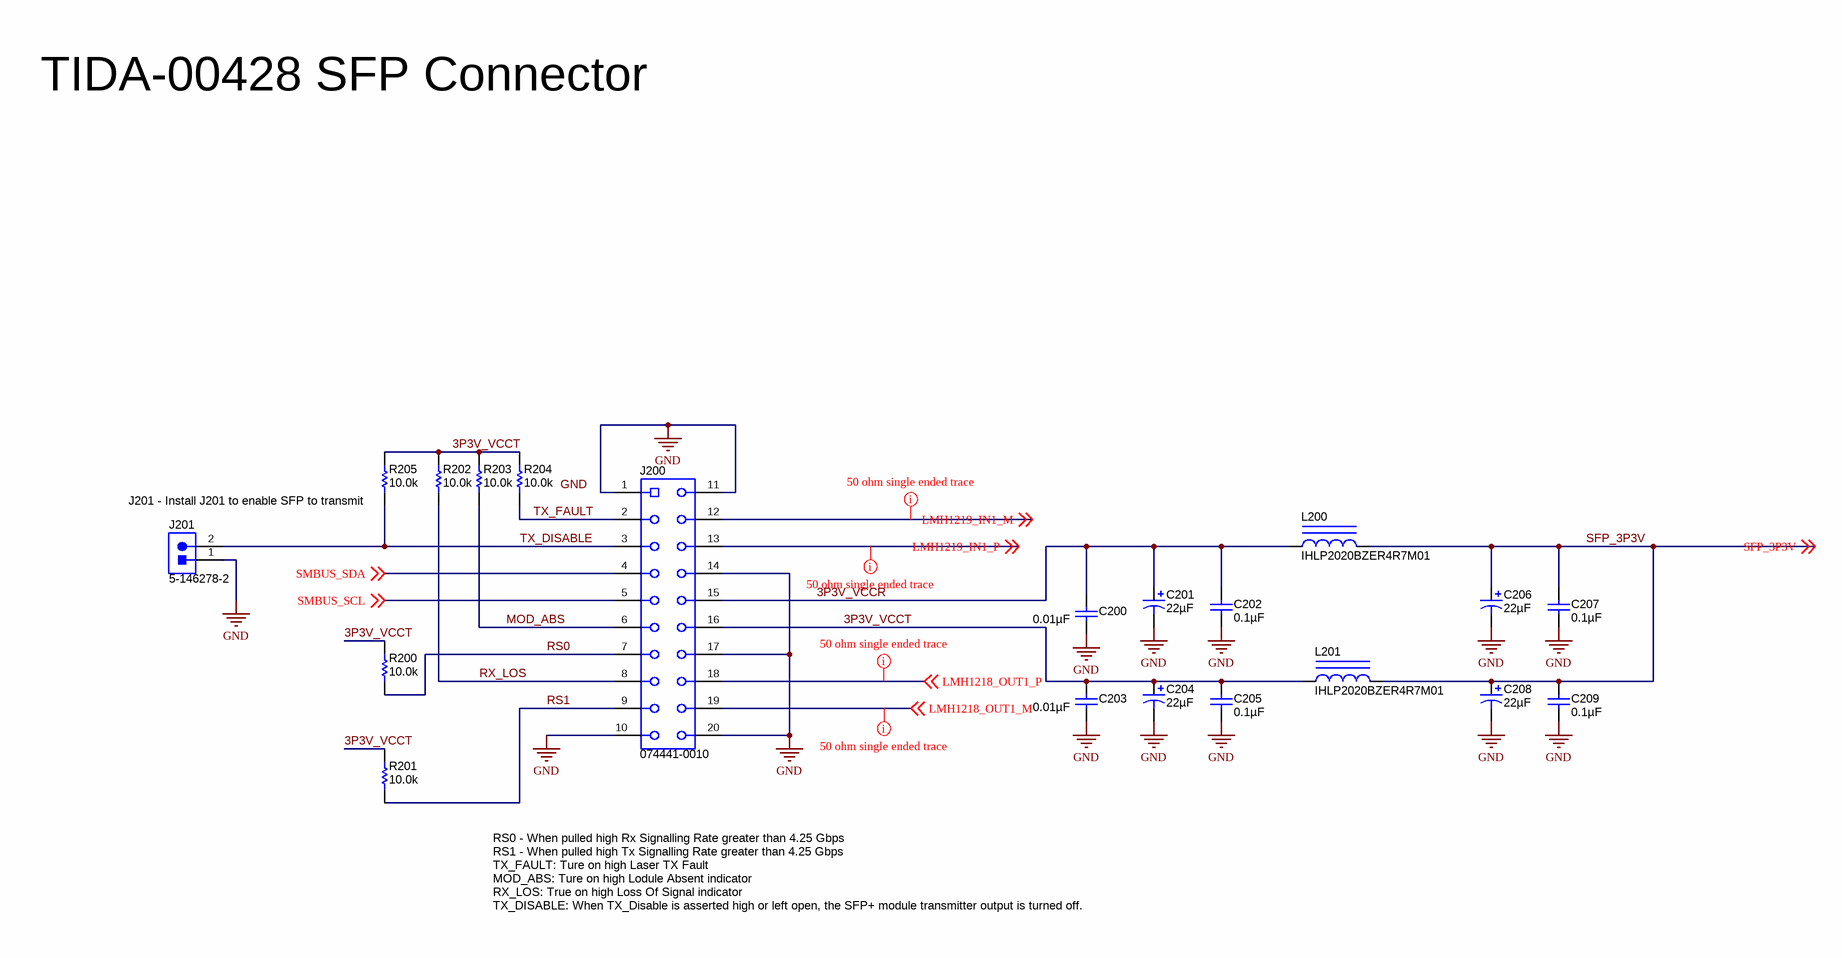
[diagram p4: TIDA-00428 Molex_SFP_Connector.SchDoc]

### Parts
C200  ValueDisplayed: 0.01µF  [C603]  (hidden comment: C1608X7R1H103K)
C201  ValueDisplayed: 22µF  [CAPSMT_62_E55]  (hidden comment: EEE-1AA220WR)
C202  ValueDisplayed: 0.1µF  [0402]  (hidden comment: C1005X5R0J104K)
C203  ValueDisplayed: 0.01µF  [C603]  (hidden comment: C1608X7R1H103K)
C204  ValueDisplayed: 22µF  [CAPSMT_62_E55]  (hidden comment: EEE-1AA220WR)
C205  ValueDisplayed: 0.1µF  [0402]  (hidden comment: C1005X5R0J104K)
C206  ValueDisplayed: 22µF  [CAPSMT_62_E55]  (hidden comment: EEE-1AA220WR)
C207  ValueDisplayed: 0.1µF  [0402]  (hidden comment: C1005X5R0J104K)
C208  ValueDisplayed: 22µF  [CAPSMT_62_E55]  (hidden comment: EEE-1AA220WR)
C209  ValueDisplayed: 0.1µF  [0402]  (hidden comment: C1005X5R0J104K)
J200  074441-0010  [Molex_074441-0010]
J201  5-146278-2  [TE_5-146278-2]
L200  IHLP2020BZER4R7M01  [IHLP-2020BZ]
L201  IHLP2020BZER4R7M01  [IHLP-2020BZ]
R200  value 10.0k  [0402]  (hidden comment: CRCW040210K0FKED)
R201  value 10.0k  [0402]  (hidden comment: CRCW040210K0FKED)
R202  value 10.0k  [0402]  (hidden comment: CRCW040210K0FKED)
R203  value 10.0k  [0402]  (hidden comment: CRCW040210K0FKED)
R204  value 10.0k  [0402]  (hidden comment: CRCW040210K0FKED)
R205  value 10.0k  [0402]  (hidden comment: CRCW040210K0FKED)

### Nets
GND: C200.1 C201.2(-) C202.2 C203.1 C204.2(-) C205.2 C206.2(-) C207.2 C208.2(-) C209.2 J200.1 J200.10 J200.11 J200.14 J200.17 J200.20 J201.1
SFP_3P3V: C206.1(+) C207.1 C208.1(+) C209.1 L200.2 L201.2 ; off-sheet SFP_3P3V
3P3V_VCCR: C200.2 C201.1(+) C202.1 J200.15 L200.1
3P3V_VCCT: C203.2 C204.1(+) C205.1 J200.16 L201.1 R200.2 R201.2 R202.2 R203.2 R204.2 R205.2
LMH1218_OUT1_M: J200.19 ; off-sheet LMH1218_OUT1_M
LMH1218_OUT1_P: J200.18 ; off-sheet LMH1218_OUT1_P
LMH1219_IN1_M: J200.12 ; off-sheet LMH1219_IN1_M
LMH1219_IN1_P: J200.13 ; off-sheet LMH1219_IN1_P
MOD_ABS: J200.6 R203.1
RS0: J200.7 R200.1
RS1: J200.9 R201.1
RX_LOS: J200.8 R202.1
SMBUS_SCL: J200.5 ; off-sheet SMBUS_SCL  [project net GPIO1/I2C_SCL]
SMBUS_SDA: J200.4 ; off-sheet SMBUS_SDA  [project net GPIO0/I2C_SDA]
TX_DISABLE: J200.3 J201.2 R205.1
TX_FAULT: J200.2 R204.1

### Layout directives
rule Undefined: LMH1218_OUT1_M, LMH1218_OUT1_P, LMH1219_IN1_M, LMH1219_IN1_P

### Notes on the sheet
- TIDA-00428 SFP Connector
- (near R205) J201 - Install J201 to enable SFP to transmit
- RS0 - When pulled high Rx Signalling Rate greater than 4.25 Gbps
  RS1 - When pulled high Tx Signalling Rate greater than 4.25 Gbps
  TX_FAULT: Ture on high Laser TX Fault
  MOD_ABS: Ture on high Lodule Absent indicator
  RX_LOS: True on high Loss Of Signal indicator
  TX_DISABLE: When TX_Disable is asserted high or left open, the SFP+ module transmitter output is turned off.
- Labels drawn without touching a wire or pin: GND

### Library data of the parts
C200 C203 = C1608X7R1H103K: as C24 on sheet TIDA-00428 USB_CNTRL
C201 C204 C206 C208 = EMVE100ADA220ME55G: as C22 on sheet TIDA-00428 USB_CNTRL
C202 C205 C207 C209 = C1005X5R0J104K: as C5 on sheet TIDA-00428 LMH1219_Schematic
J200 = 074441-0010: Receptacle, 0.8mm, 10x2, Gold, R/A, SMT; Manufacturer: Molex; SymbolCreator: a0412235; U/M: EA
J201 = 5-146278-2: as J9 on sheet TIDA-00428 LMH1219_Schematic
L200 L201 = IHLP2020BZER4R7M01: Inductor, Shielded Drum Core, Powdered Iron, 4.7 µH, 2.8 A, 0.108 ohm, SMD; Manufacturer: Vishay-Dale; Value: 4.7uH; Ind_H: 4.7E-6; ValueDisplayed: 4.7µH; Imax_A: 2.8; Irms: 2.8A @ 40C rise; Isat: 5A @ 20% inductance drop; DCR_ohm: 0.108; Value2: 2.8A
R200-R205 = CRCW040220K0FKED: RES, 10.0k ohm, 1%, 0.063W, 0402; Manufacturer: Vishay-Dale; CompType: Resistor; Res_ohm: 20000; Value_Code: 20k0; Tolerance_%: 1; Power_W: 0.063; VDC_V: 50; TempCo: 100 ppm/C; EIA_Code: E96; U/M: EA

## Sheet TIDA-00428 Hardware_ANSI-B.SchDoc: TIDA-00428 - Hardware
size 431 x 279 mm; Date: Not shown in title block; ApprovedBy: Not shown in title block; CheckedBy: Not shown in title block; Author: Not shown in title block; CompanyName: Not shown in title block; Engineer: Not shown in title block; Organization: Not shown in title block; Address1: Not shown in title block; Address2: Not shown in title block; Address3: Not shown in title block; Address4: Not shown in title block; DocumentNumber: 1; Revision: Use project parameter SCH_Rev; SheetNumber: 7; SheetTotal: 7; PageSetup: Record=PageOptions¦CenterHorizontal=True¦CenterVertical=True¦PrintScale=0.59¦XCorrection=1.00¦YCorrection=1.00¦PrintKind=0¦BorderSize=5000000¦LeftOffset=0¦BottomOffset=0¦Orientation=2¦PaperLength=1000¦PaperWidth=1000¦Scale=100¦PaperSource=15¦PrintQuality=600¦MediaType=1¦DitherType=10¦PaperKind=Letter¦PrintScaleMode=1
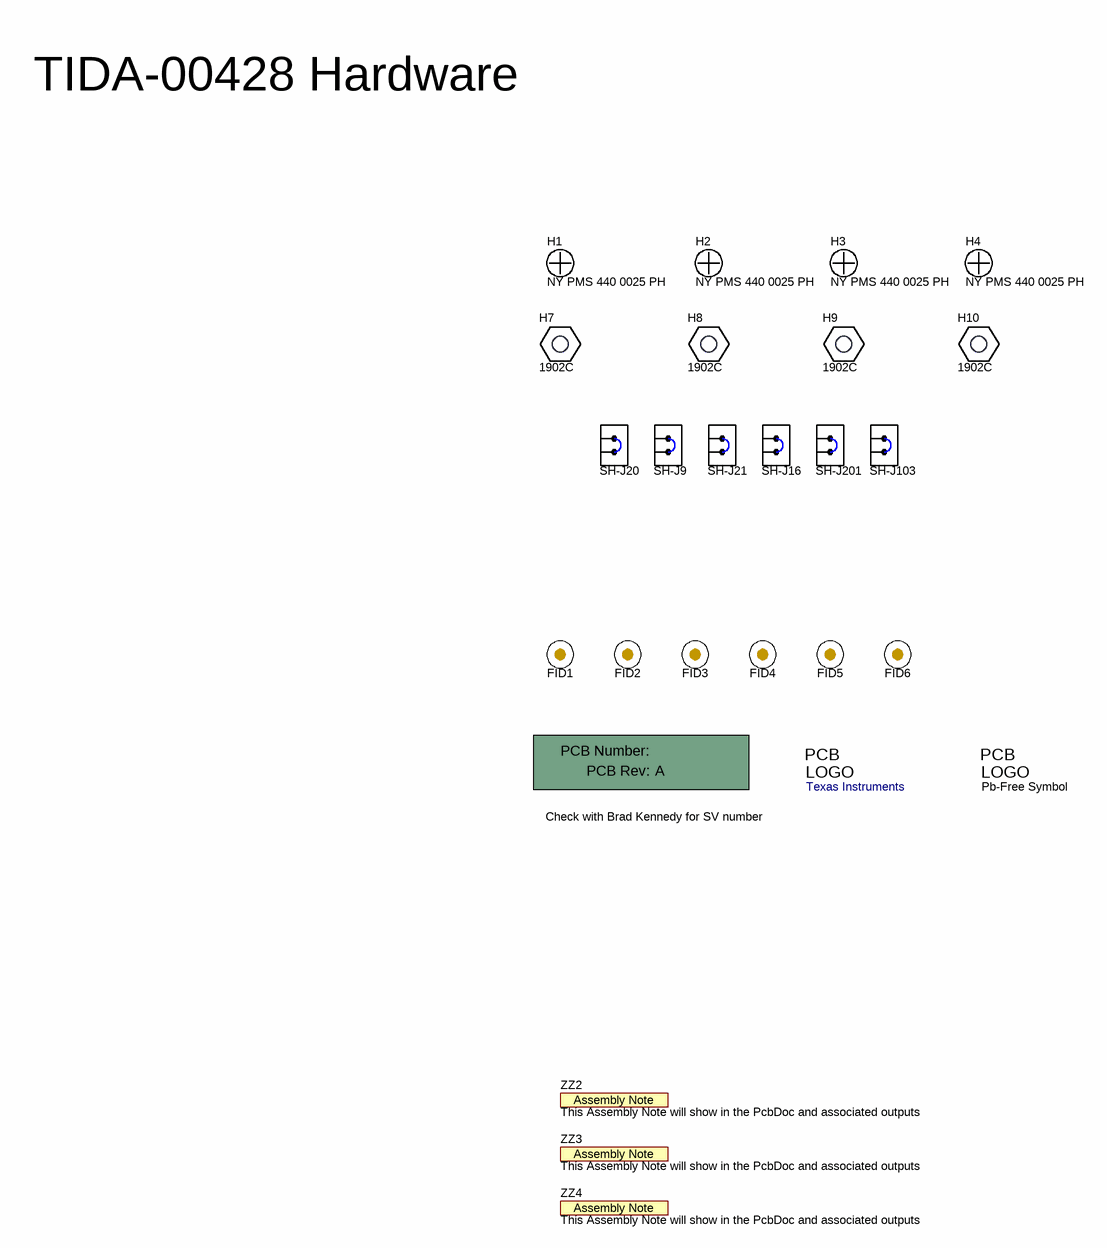
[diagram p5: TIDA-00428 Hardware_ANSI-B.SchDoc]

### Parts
!PCB  Printed Circuit Board  (value not drawn)  (mechanical)
FID1  Fiducial  [Fiducial10-30]  (value not drawn)
FID2  Fiducial  [Fiducial10-30]  (value not drawn)
FID3  Fiducial  [Fiducial10-30]  (value not drawn)
FID4  Fiducial  [Fiducial10-30]  (value not drawn)
FID5  Fiducial  [Fiducial10-30]  (value not drawn)
FID6  Fiducial  [Fiducial10-30]  (value not drawn)
H1  NY PMS 440 0025 PH  [NY PMS 440 0025 PH]
H2  NY PMS 440 0025 PH  [NY PMS 440 0025 PH]
H3  NY PMS 440 0025 PH  [NY PMS 440 0025 PH]
H4  NY PMS 440 0025 PH  [NY PMS 440 0025 PH]
H7  1902C  [Keystone_1902C]
H8  1902C  [Keystone_1902C]
H9  1902C  [Keystone_1902C]
H10  1902C  [Keystone_1902C]
Logo1  Texas Instruments  [TI_Stacked_SolderMask_Medium]  (no BOM)
Logo2  Pb-Free Symbol  [Pb-Free_Overlay_Small]  (no BOM)
SH-J9  969102-0000-DA  [SNT-100-BK-G]  (value not drawn)
SH-J16  969102-0000-DA  [SNT-100-BK-G]  (value not drawn)
SH-J20  969102-0000-DA  [SNT-100-BK-G]  (value not drawn)
SH-J21  969102-0000-DA  [SNT-100-BK-G]  (value not drawn)
SH-J103  969102-0000-DA  [SNT-100-BK-G]  (value not drawn)
SH-J201  969102-0000-DA  [SNT-100-BK-G]  (value not drawn)
ZZ2  This Assembly Note will show in the PcbDoc and associated outputs  [AssemblyNote]  (no BOM)
ZZ3  This Assembly Note will show in the PcbDoc and associated outputs  [AssemblyNote]  (no BOM)
ZZ4  This Assembly Note will show in the PcbDoc and associated outputs  [AssemblyNote]  (no BOM)

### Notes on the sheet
- TIDA-00428 Hardware
- (near !PCB) Check with Brad Kennedy for SV number

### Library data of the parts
!PCB = PCB: Manufacturer: Any; SymbolCreator: a0414036
FID1-FID6 = Fiducial: Fiducial mark.  There is nothing to buy or mount.; SymbolCreator: codlsc
H1-H4 = NY PMS 440 0025 PH: Machine Screw, Round, #4-40 x 1/4, Nylon, Philips panhead; Manufacturer: B&F Fastener Supply; CompType: Hardware; SymbolCreator: codlsc; U/M: EA
H7-H10 = 1902C: Standoff, Hex, 0.5"L #4-40 Nylon; Manufacturer: Keystone; CompType: Hardware; SymbolCreator: a0412235
Logo1 = TI_Logo: Texas Instrument Corporate Signature; SymbolCreator: a0412235
Logo2 = Pb-Free: SymbolCreator: a0412235
SH-J9 SH-J16 SH-J20 SH-J21 SH-J103 SH-J201 = 969102-0000-DA: Shunt, 100mil, Gold plated, Black; Manufacturer: 3M; Alternate Manufacturer: Samtec; Value: 1x2; Note: You can "mate" this to a header by matching the designator.  i.e. use SH-J3 for header J3
ZZ2-ZZ4 = AssemblyNote: SymbolCreator: codlsc

## Sheet TIDA-00428 Power.SchDoc: TIDA-00428 - Power
size 431 x 279 mm; Date: Not shown in title block; ApprovedBy: Not shown in title block; CheckedBy: Not shown in title block; Author: Not shown in title block; CompanyName: Not shown in title block; Engineer: Not shown in title block; Organization: Not shown in title block; Address1: Not shown in title block; Address2: Not shown in title block; Address3: Not shown in title block; Address4: Not shown in title block; DocumentNumber: 1; Revision: Use project parameter SCH_Rev; SheetNumber: 6; SheetTotal: 7; PageSetup: Record=PageOptions¦CenterHorizontal=True¦CenterVertical=True¦PrintScale=1.00¦XCorrection=1.00¦YCorrection=1.00¦PrintKind=0¦BorderSize=5000000¦LeftOffset=0¦BottomOffset=0¦Orientation=2¦PaperLength=1000¦PaperWidth=1000¦Scale=100¦PaperSource=15¦PrintQuality=600¦MediaType=1¦DitherType=10¦PaperKind=Letter¦PrintScaleMode=1
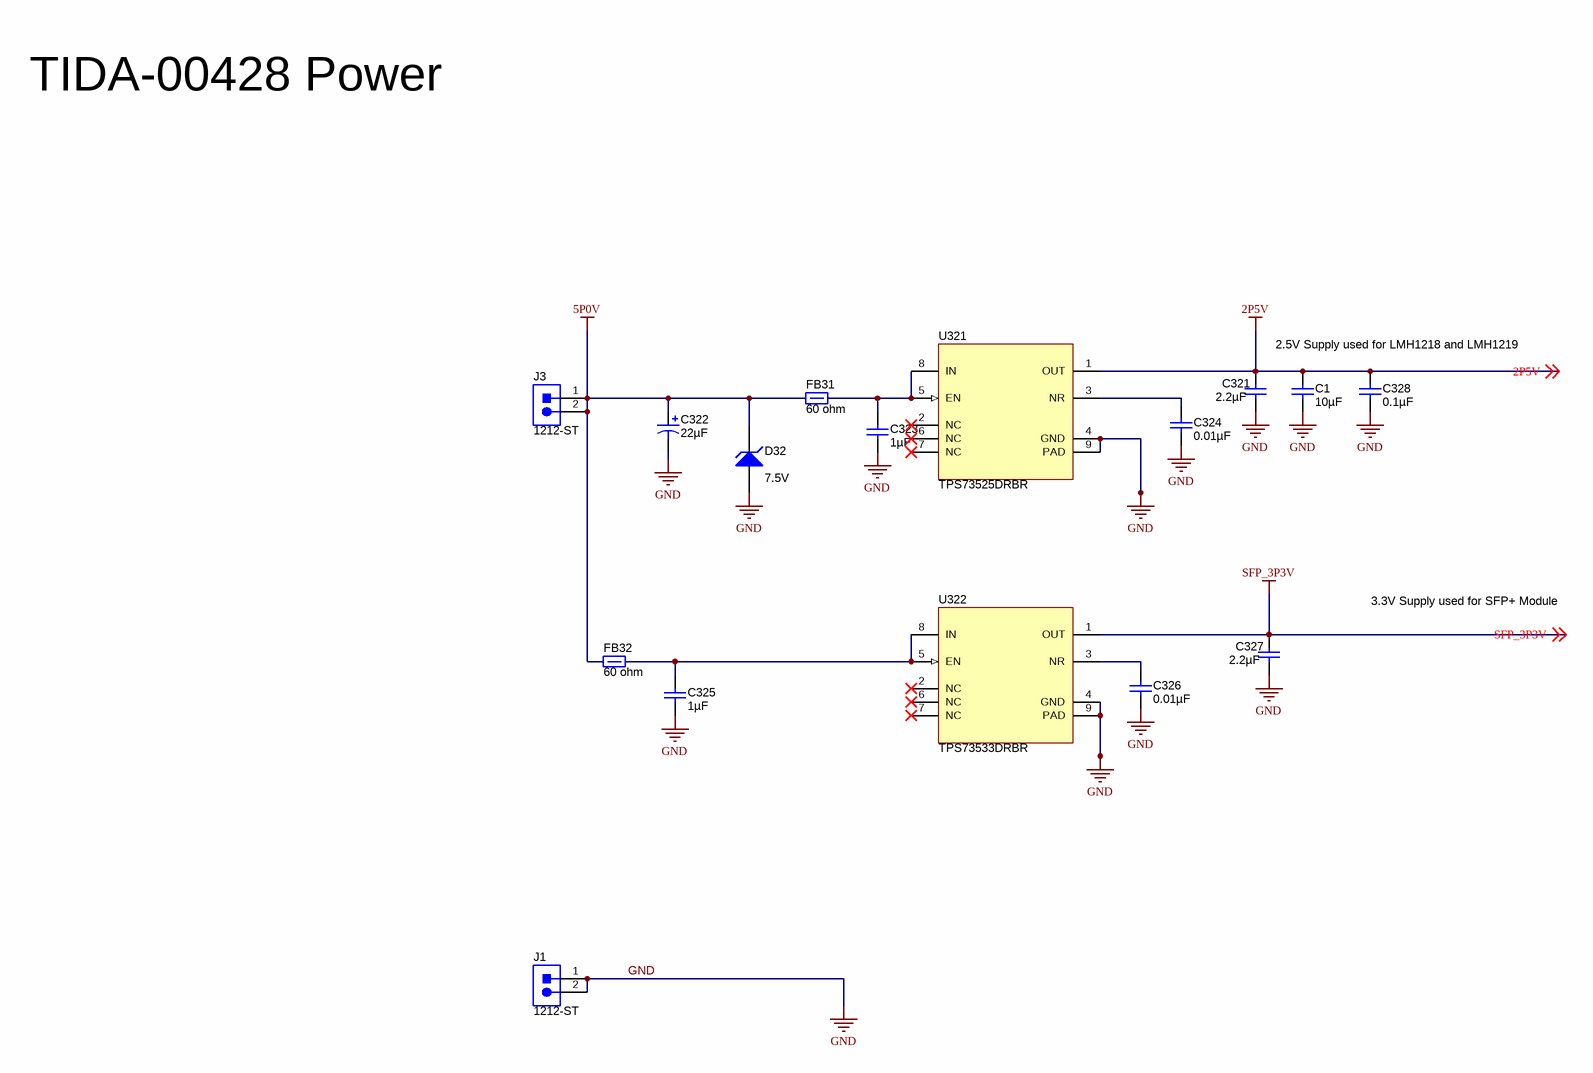
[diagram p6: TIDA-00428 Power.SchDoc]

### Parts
C1  ValueDisplayed: 10µF  [0805_HV]  (hidden comment: 0805YD106MAT2A)
C321  ValueDisplayed: 2.2µF  [C0805]  (hidden comment: 0805YD225KAT2A)
C322  ValueDisplayed: 22µF  [CAPSMT_62_E55]  (hidden comment: EEE-1AA220WR)
C323  ValueDisplayed: 1µF  [C0805]  (hidden comment: C2012X7R1C105K/1.25)
C324  ValueDisplayed: 0.01µF  [C603]  (hidden comment: C1608X7R1H103K)
C325  ValueDisplayed: 1µF  [C0805]  (hidden comment: C2012X7R1C105K/1.25)
C326  ValueDisplayed: 0.01µF  [C603]  (hidden comment: C1608X7R1H103K)
C327  ValueDisplayed: 2.2µF  [C0805]  (hidden comment: 0805YD225KAT2A)
C328  ValueDisplayed: 0.1µF  [0402]  (hidden comment: C1005X5R0J104K)
D32  value 7.5V  [SMB]  (hidden comment: 1SMB5922BT3G)
FB31  value 60 ohm  [0603]  (hidden comment: BK1608HS600-T)
FB32  value 60 ohm  [0603]  (hidden comment: BK1608HS600-T)
J1  1212-ST  [Keystone_1212-ST]
J3  1212-ST  [Keystone_1212-ST]
U321  TPS73525DRBR  [DRB0008A]
U322  TPS73533DRBR  [DRB0008A]

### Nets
2P5V: C1.1 C321.2 C328.1 U321.1(OUT) ; off-sheet 2P5V
5P0V: C322.1(+) D32.1(K) FB31.1 FB32.1 J3.1 J3.2
GND: C1.2 C321.1 C322.2(-) C323.1 C324.1 C325.1 C326.1 C327.1 C328.2 D32.2(A) J1.1 J1.2 U321.4(GND) U321.9(PAD) U322.4(GND) U322.9(PAD)
SFP_3P3V: C327.2 U322.1(OUT) ; off-sheet SFP_3P3V
NetC323_2: C323.2 FB31.2 U321.5(EN) U321.8(IN)
NetC324_2: C324.2 U321.3(NR)
NetC325_2: C325.2 FB32.2 U322.5(EN) U322.8(IN)
NetC326_2: C326.2 U322.3(NR)

Not connected (* = marked no-connect by the designer): U321 2(NC)* 6(NC)* 7(NC)*; U322 2(NC)* 6(NC)* 7(NC)*

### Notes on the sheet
- TIDA-00428 Power
- 2.5V Supply used for LMH1218 and LMH1219
- 3.3V Supply used for SFP+ Module

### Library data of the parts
C1 = 0805YD106MAT2A: CAP, CERM, 10uF, 16V, +/-20%, X5R, 0805; Manufacturer: AVX; Polarized: N; CompType: Capacitor; U/M: EA; Cap_F: 0.00001; Tolerance_%: 20; Value1: Unknown; VDC_V: 16; TaMin_C: -55; TaMax_C: 85; Cap_Case: 0805
C321 C327 = 0805YD225KAT2A: as C21 on sheet TIDA-00428 USB_CNTRL
C322 = EMVE100ADA220ME55G: as C22 on sheet TIDA-00428 USB_CNTRL
C323 C325 = C2012Y5V1C105Z/0.85: as C23 on sheet TIDA-00428 USB_CNTRL
C324 C326 = C1608X7R1H103K: as C24 on sheet TIDA-00428 USB_CNTRL
C328 = C1005X5R0J104K: as C5 on sheet TIDA-00428 LMH1219_Schematic
D32 = 1SMB5922BT3G: as D2 on sheet TIDA-00428 USB_CNTRL
FB31 FB32 = BK1608HS600-T: as FB1 on sheet TIDA-00428 USB_CNTRL
J1 J3 = 1212-ST: Disconnect Terminal, 5.08mm, 2x1, Tin, TH; Manufacturer: Keystone; SymbolCreator: a0412235; U/M: EA
U321 = TPS73525DRBR: 500mA, Low Quiescent Current, Ultra-Low Noise, High PSRR Low-Dropout Linear Regulator, DRB0008A; Manufacturer: Texas Instruments; Alternate PartNumber: TPS73525DRBT; SymbolCreator: Altium; CompType: IC; U/M: EA
U322 = TPS73533DRBR: as U2 on sheet TIDA-00428 USB_CNTRL

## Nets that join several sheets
2P5V: TIDA-00428 LMH1219_Schematic (7 pins), TIDA-00428 LMH1218_Schematic (5 pins), TIDA-00428 Power (C1.1 C321.2 C328.1 U321.1)
GND: TIDA-00428 LMH1219_Schematic (27 pins), TIDA-00428 USB_CNTRL (29 pins), TIDA-00428 LMH1218_Schematic (23 pins), TIDA-00428 Molex_SFP_Connector (17 pins), TIDA-00428 Power (16 pins)
SFP_3P3V: TIDA-00428 Molex_SFP_Connector (6 pins), TIDA-00428 Power (C327.2 U322.1)
USB_3P3V: TIDA-00428 LMH1219_Schematic (J8.5 R1.2 R2.2), TIDA-00428 USB_CNTRL (9 pins)
GPIO0/I2C_SDA: TIDA-00428 LMH1219_Schematic (J8.10 J9.1 U1.10), TIDA-00428 USB_CNTRL (U4.46), TIDA-00428 LMH1218_Schematic (U100.4), TIDA-00428 Molex_SFP_Connector (J200.4)
GPIO1/I2C_SCL: TIDA-00428 LMH1219_Schematic (J8.9 J21.2 U1.21), TIDA-00428 USB_CNTRL (U4.47), TIDA-00428 LMH1218_Schematic (U100.3), TIDA-00428 Molex_SFP_Connector (J200.5)
LMH1218_OUT1_M: TIDA-00428 LMH1218_Schematic (U100.22), TIDA-00428 Molex_SFP_Connector (J200.19)
LMH1218_OUT1_P: TIDA-00428 LMH1218_Schematic (U100.23), TIDA-00428 Molex_SFP_Connector (J200.18)
LMH1219_IN1_M: TIDA-00428 LMH1219_Schematic (U1.5), TIDA-00428 Molex_SFP_Connector (J200.12)
LMH1219_IN1_P: TIDA-00428 LMH1219_Schematic (U1.4), TIDA-00428 Molex_SFP_Connector (J200.13)
LMH1219_OUT0_M: TIDA-00428 LMH1219_Schematic (U1.17), TIDA-00428 LMH1218_Schematic (C101.2)
LMH1219_OUT0_P: TIDA-00428 LMH1219_Schematic (U1.18), TIDA-00428 LMH1218_Schematic (C100.2)
MODE_SEL: TIDA-00428 LMH1219_Schematic (R12.2 U1.6), TIDA-00428 LMH1218_Schematic (R104.2 U100.1)

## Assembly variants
001: not fitted FID1 FID2 FID3 FID4 FID5 FID6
